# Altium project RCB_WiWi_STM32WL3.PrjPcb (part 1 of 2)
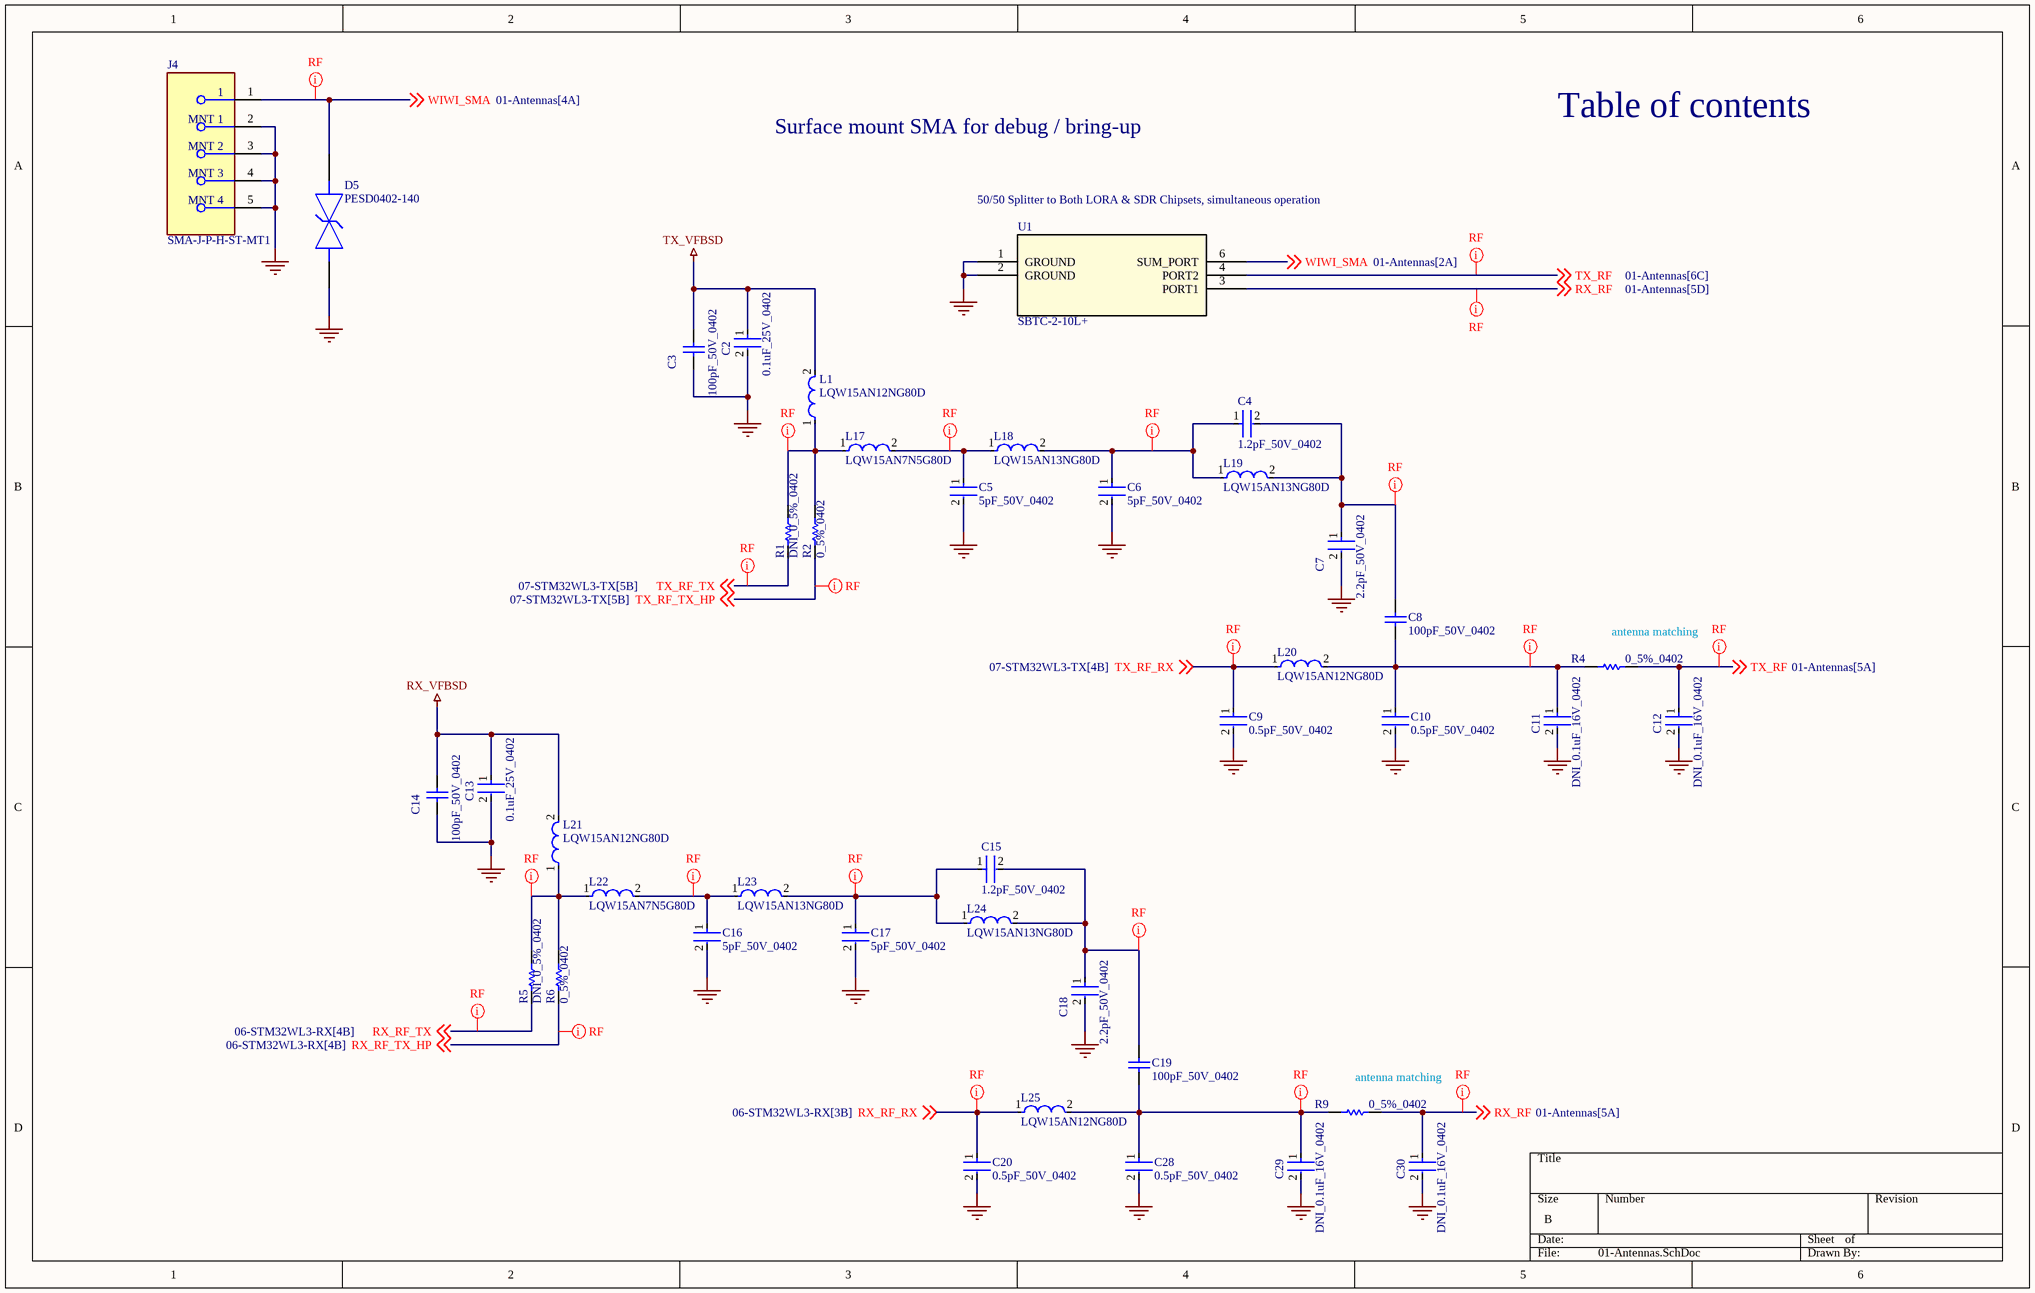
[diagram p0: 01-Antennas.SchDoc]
prjCompanyName: Meta Platforms Technologies, LLC.; prjContactAddress1: 9845 Willows Road NE; prjContactAddress2: Redmond, WA 98052; prjContactEmail: Contact Email; prjContactPhone: (...)-...-....; prjElectricalEngineer: Electical Engineer; prjElectricalEngineerEmail: Electical Engineer Email; prjLayoutEngineer: Layout Engineer; prjLayoutEngineerEmail: Layout Engineer Email; prjMechanicalEngineer: Mechanical Engineer; prjMechanicalEngineerEmail: Mechanical Engineer Email; prjPCB_IPN: 844-XXXXX-XX; prjPCB_Name: PCB Name; prjPCB_Revision: X1; prjProjectName: Project Name; prjSchematic_IPN: 846-XXXXX-XX; prjSchematic_Revision: X1; XprjPCBA_IPN: Set v_prjPCBA_IPN in variant parameters; XprjPCBA_Revision: Set v_prjPCBA_Revision in variant parameters
8 sheets, 342 parts. Net scope: global (net labels, ports and power ports of the same name join across sheets).
Board file: RCB_WiWi_STM32WL3_V1.PcbDoc
Sheets:
  01-Antennas.SchDoc
  02-8A34004_DPLL-1.SchDoc
  03-8A34004_DPLL-2.SchDoc
  04-TCXO_Crystal.SchDoc
  05-USB-Prog.SchDoc
  06-STM32WL3-RX.SchDoc
  07-STM32WL3-TX.SchDoc
  08-Power.SchDoc

## Sheet 01-Antennas.SchDoc
size B; SheetNumber: 1; SheetTotal: 8; SPICEModelCacheELOCFEDZ: <root> / <DocumentId>ELOCFEDZ</DocumentId> / </root>

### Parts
C2  0.1uF_25V_0402  [FP-0402-L_1_0_1-W_0_5_0_1-IPC_C]
C3  100pF_50V_0402  [CAPC1005X55X25ML05T10]
C4  1.2pF_50V_0402  [FP-GJM155-0_05-IPC_A]
C5  5pF_50V_0402  [FP-GJM155-0_05-IPC_B]
C6  5pF_50V_0402  [FP-GJM155-0_05-IPC_B]
C7  2.2pF_50V_0402  [FP-GJM155-0_05-IPC_C]
C8  100pF_50V_0402  [CAPC1005X55X25ML05T10]
C9  0.5pF_50V_0402  [FP-GJM155-0_05-MFG]
C10  0.5pF_50V_0402  [FP-GJM155-0_05-MFG]
C11  DNI_0.1uF_16V_0402  [FP-C0402-BB-MFG]  (no BOM)
C12  DNI_0.1uF_16V_0402  [FP-C0402-BB-MFG]  (no BOM)
C13  0.1uF_25V_0402  [FP-0402-L_1_0_1-W_0_5_0_1-IPC_C]
C14  100pF_50V_0402  [CAPC1005X55X25ML05T10]
C15  1.2pF_50V_0402  [FP-GJM155-0_05-IPC_A]
C16  5pF_50V_0402  [FP-GJM155-0_05-IPC_B]
C17  5pF_50V_0402  [FP-GJM155-0_05-IPC_B]
C18  2.2pF_50V_0402  [FP-GJM155-0_05-IPC_C]
C19  100pF_50V_0402  [CAPC1005X55X25ML05T10]
C20  0.5pF_50V_0402  [FP-GJM155-0_05-MFG]
C28  0.5pF_50V_0402  [FP-GJM155-0_05-MFG]
C29  DNI_0.1uF_16V_0402  [FP-C0402-BB-MFG]  (no BOM)
C30  DNI_0.1uF_16V_0402  [FP-C0402-BB-MFG]  (no BOM)
D5  PESD0402-140  [FP-PESD0402-MFG]
J4  SMA-J-P-H-ST-MT1  [FP-SMA-J-P-H-ST-MT1-MFG]
L1  LQW15AN12NG80D  [FP-LQW15AN_80-MFG]
L17  LQW15AN7N5G80D  [FP-LQW15AN_80-MFG]
L18  LQW15AN13NG80D  [FP-LQW15AN_80-MFG]
L19  LQW15AN13NG80D  [FP-LQW15AN_80-MFG]
L20  LQW15AN12NG80D  [FP-LQW15AN_80-MFG]
L21  LQW15AN12NG80D  [FP-LQW15AN_80-MFG]
L22  LQW15AN7N5G80D  [FP-LQW15AN_80-MFG]
L23  LQW15AN13NG80D  [FP-LQW15AN_80-MFG]
L24  LQW15AN13NG80D  [FP-LQW15AN_80-MFG]
L25  LQW15AN12NG80D  [FP-LQW15AN_80-MFG]
R1  DNI_0_5%_0402  [RESC1005X40X25NL05T10]  (no BOM)
R2  0_5%_0402  [RESC1005X40X25NL05T10]
R4  0_5%_0402  [RESC1005X40X25NL05T10]
R5  DNI_0_5%_0402  [RESC1005X40X25NL05T10]  (no BOM)
R6  0_5%_0402  [RESC1005X40X25NL05T10]
R9  0_5%_0402  [RESC1005X40X25NL05T10]
U1  SBTC-2-10L+  [AT1029_MNC]

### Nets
GND: C2.2 C3.1 C5.2 C6.2 C7.2 C9.2 C10.2 C11.2 C12.2 C13.2 C14.1 C16.2 C17.2 C18.2 C20.2 C28.2 C29.2 C30.2 D5.1 J4.2(MNT_1) J4.3(MNT_2) J4.4(MNT_3) J4.5(MNT_4) U1.1(GROUND) U1.2(GROUND)
RX_VFBSD: C13.1 C14.2 L21.2
TX_VFBSD: C2.1 C3.2 L1.2
RX_RF: C30.1 R9.2 U1.3(PORT1) ; off-sheet RX_RF
RX_RF_RX: C20.1 L25.1 ; off-sheet RX_RF_RX
RX_RF_TX: R5.1 ; off-sheet RX_RF_TX
RX_RF_TX_HP: R6.1 ; off-sheet RX_RF_TX_HP
TX_RF: C12.1 R4.2 U1.4(PORT2) ; off-sheet TX_RF
TX_RF_RX: C9.1 L20.1 ; off-sheet TX_RF_RX
TX_RF_TX: R1.1 ; off-sheet TX_RF_TX
TX_RF_TX_HP: R2.1 ; off-sheet TX_RF_TX_HP
WIWI_SMA: D5.2 J4.1 U1.6(SUM_PORT) ; off-sheet WIWI_SMA
NetC4_1: C4.1 C6.1 L18.2 L19.1
NetC4_2: C4.2 C7.1 C8.2 L19.2
NetC5_1: C5.1 L17.2 L18.1
NetC8_1: C8.1 C10.1 C11.1 L20.2 R4.1
NetC15_1: C15.1 C17.1 L23.2 L24.1
NetC15_2: C15.2 C18.1 C19.2 L24.2
NetC16_1: C16.1 L22.2 L23.1
NetC19_1: C19.1 C28.1 C29.1 L25.2 R9.1
NetL1_1: L1.1 L17.1 R1.2 R2.2
NetL21_1: L21.1 L22.1 R5.2 R6.2

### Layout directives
net class RF: NetC4_1, NetC4_2, NetC5_1, NetC8_1, NetC15_1, NetC15_2, NetC16_1, NetC19_1, NetL1_1, NetL21_1, RX_RF, RX_RF_RX, RX_RF_TX, RX_RF_TX_HP, TX_RF, TX_RF_RX, TX_RF_TX, TX_RF_TX_HP, WIWI_SMA

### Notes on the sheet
- Surface mount SMA for debug / bring-up
- Table of contents
- 50/50 Splitter to Both LORA & SDR Chipsets, simultaneous operation
- (near R4) antenna matching
- (near R9) antenna matching

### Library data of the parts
C2 C13 = CMP-2008-02519-2: General Purpose Ceramic Capacitor, 0402, 100nF, 10%, X7R, 15%, 25V
C3 C8 C14 C19 = CMP-2008-03915-1: Manufacturer: Murata; Part Number: GRM1555C1H101JA01D
C4 C15 = CMP-2008-03815-2: Multi-Layer Ceramic Capacitor 1.2pF C0G  ±0.05pF 0402 Paper T/R; Voltage Rating: 50V
C5 C6 C16 C17 = CMP-06035-005630-1: Multi-Layer Ceramic Capacitor 5pF C0G  ±0.05pF 0402 Paper T/R; Voltage Rating (DC): 50V
C7 C18 = CMP-2008-03837-2: Multi-Layer Ceramic Capacitor 2.2pF C0G  ±0.05pF 0402 Paper T/R; Voltage Rating: 50V
C9 C10 C20 C28 = CMP-2008-03904-2: Multi-Layer Ceramic Capacitor 0.5pF C0G  ±0.1pF 0402 Paper T/R; Voltage Rating (DC): 50V; Temperature Coefficient: 30ppm/°C
C11 C12 C29 C30 = CMP-1034-02068-3: CAP CER 0.1UF 16V 5% X7R 0402; Manufacturer: Kemet; Manufacturer Part Number: C0402C104J4RACTU; Value: 0.10 μF; Temperature Coefficient: 15%; Tolerance: 0.05; Material: Ceramic
D5 = CMP-08607-000011-1: TVS DIODE 14V 40V 0402; Manufacturer: Littelfuse Inc.; Automotive Grade: Grade 1; Capacitance: 0.25pF; Value: 0.25pF; Direction: Bidirectional; Number Of Channels: 1
J4 = CMP-02754-000007-1: CONN SMA JACK STR 50 OHM SMD; Dielectric Material: PTFE; Voltage Rating: 335V; Body Material: Brass; Center Contact Plating: Gold; Impedance: 50R; Number of Ports: 1; Max Frequency: 20GHz
L1 L20 L21 L25 = CMP-06042-001817-1: Wire Wound RF Inductor 12nH ±2% 1240mA 0.093Ω 0402 (1005); Test Frequency: 100MHz; DC Resistance (DCR): 93mR; Self Resonant Frequency: 5.2GHz; Shielding: Unshielded; Max DC Current: 1.24A; Q Factor: 30; Core Material: Ferrite
L17 L22 = CMP-06042-000856-1: Wire Wound RF Inductor 7.5nH ±2% 1700mA 0.05Ω 0402 (1005); Max DC Current: 1.7A; Shielding: Unshielded; Core Material: Ferrite; Self Resonant Frequency: 7GHz; DC Resistance (DCR): 50mR; Test Frequency: 100MHz; Q Factor: 35
L18 L19 L23 L24 = CMP-06042-008137-1: Wire Wound RF Inductor 13nH ±2% 1240mA 0.093Ω 0402 (1005); Core Material: Ferrite; Q Factor: 30; DC Resistance (DCR): 93mR; Current Rating: 1.24A; Shielding: Unshielded; Test Frequency: 100MHz; Self Resonant Frequency: 5.2GHz
R1 R2 R4-R6 R9 = CMP-2002-06457-1: Manufacturer: Panasonic; Part Number: ERJ-U020R00X
U1 = SBTC-2-10L+: No Description Available; Mfr_Name: Mini Circuits

## Sheet 02-8A34004_DPLL-1.SchDoc
size B; SheetNumber: 2; SheetTotal: 8
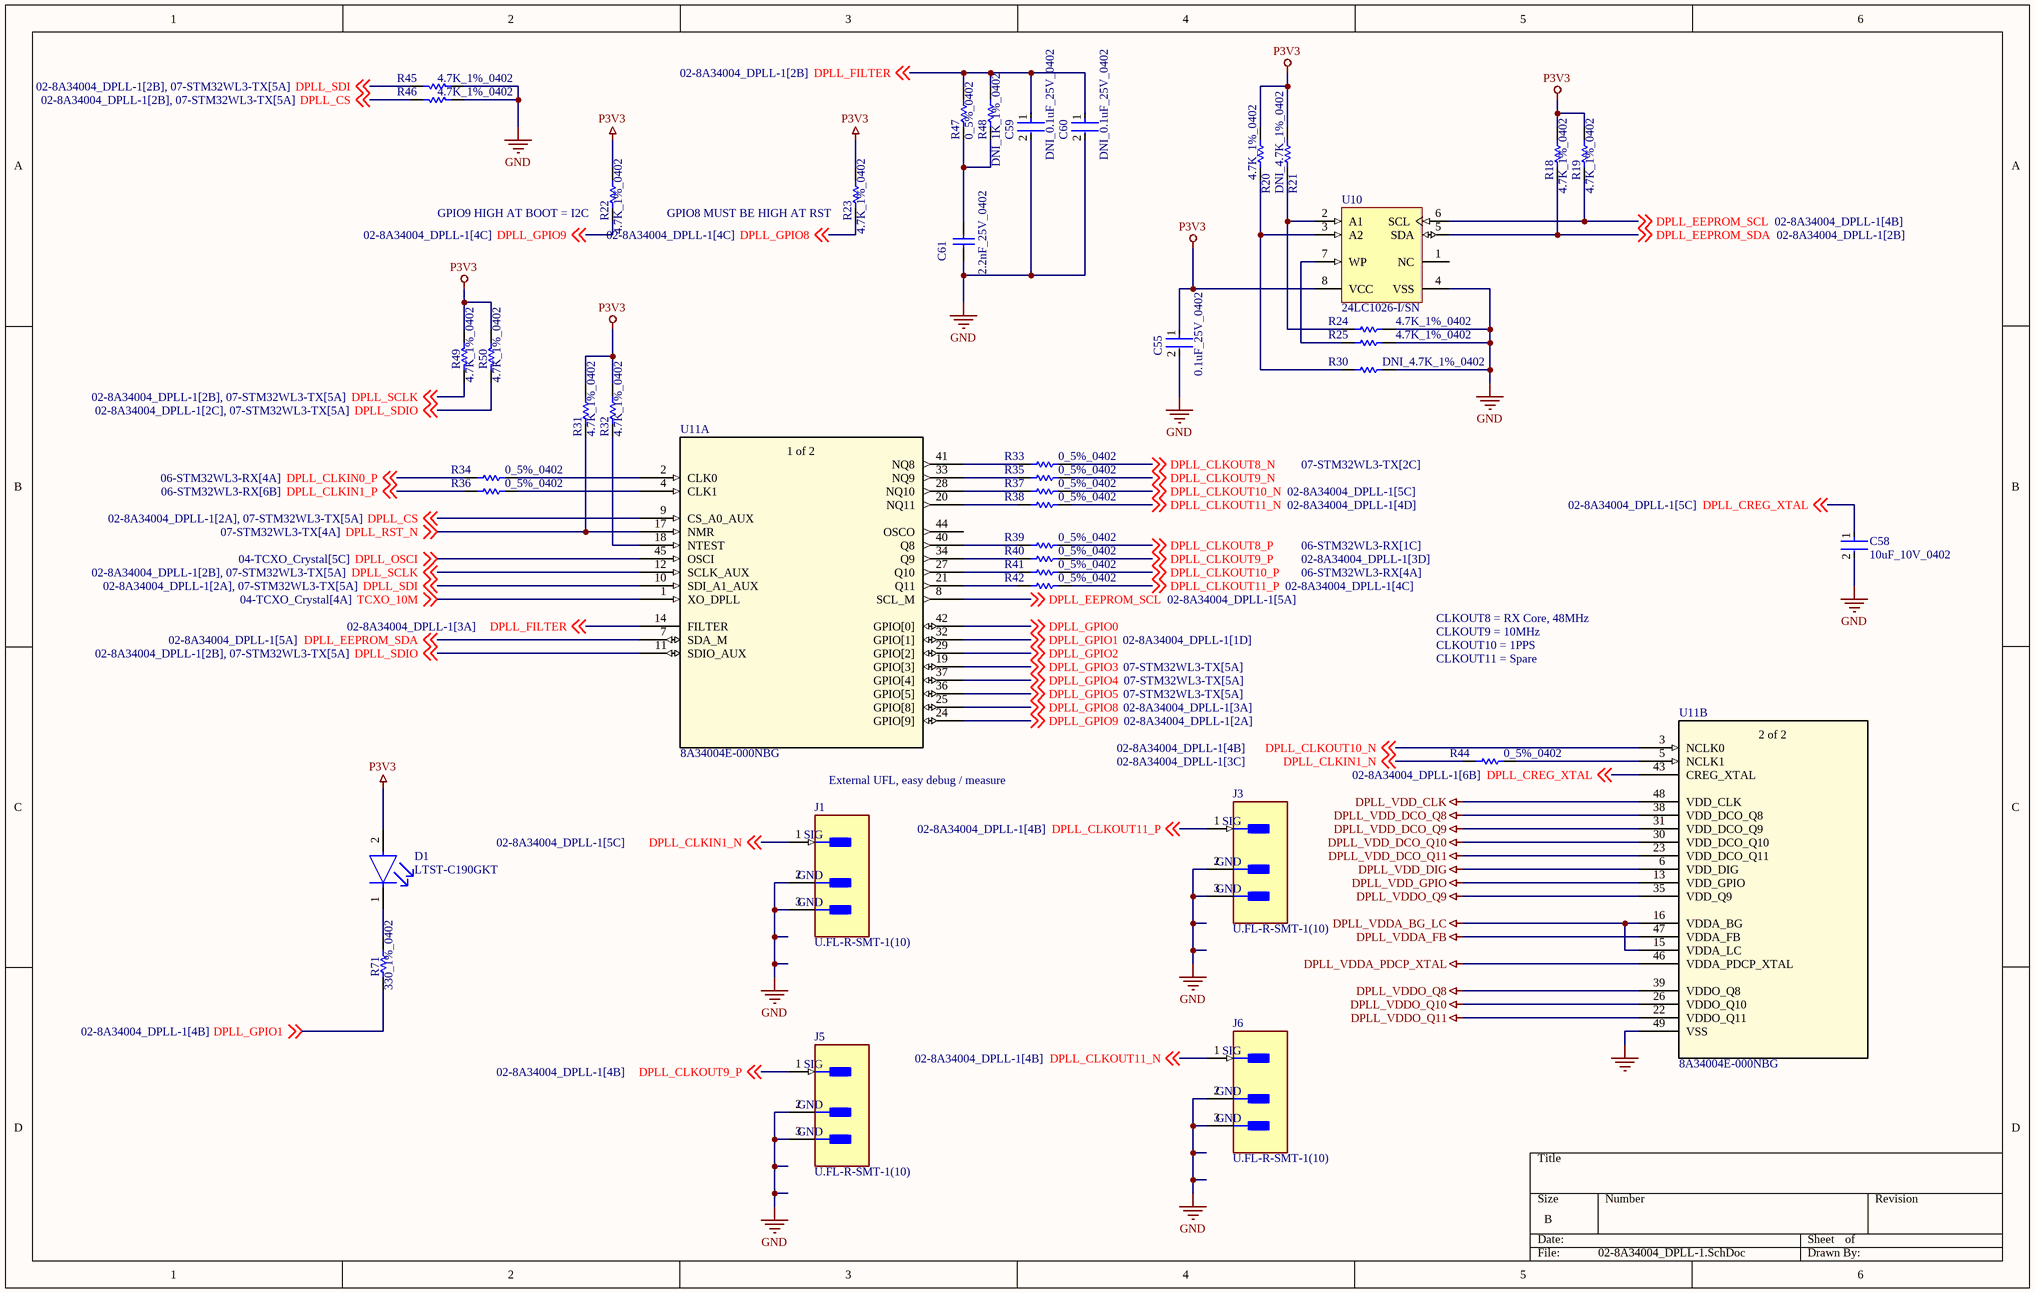
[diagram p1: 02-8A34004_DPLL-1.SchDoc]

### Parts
C55  0.1uF_25V_0402  [FP-0402-L_1_0_1-W_0_5_0_1-IPC_C]
C58  10uF_10V_0402  [FP-CL05A106MP5NUNC-MFG]
C59  DNI_0.1uF_25V_0402  [FP-0402-L_1_0_1-W_0_5_0_1-IPC_C]  (no BOM)
C60  DNI_0.1uF_25V_0402  [FP-0402-L_1_0_1-W_0_5_0_1-IPC_C]  (no BOM)
C61  2.2nF_25V_0402  [CAPC1005X56X25LL10T15]
D1  LTST-C190GKT  [FP-LTST-C190GKT-MFG]
J1  U.FL-R-SMT-1(10)  [FP-U_FL-R-SMT-1_10-MFG]
J3  U.FL-R-SMT-1(10)  [FP-U_FL-R-SMT-1_10-MFG]
J5  U.FL-R-SMT-1(10)  [FP-U_FL-R-SMT-1_10-MFG]
J6  U.FL-R-SMT-1(10)  [FP-U_FL-R-SMT-1_10-MFG]
R18  4.7K_1%_0402  [RESC1005X40X25NL10T10]
R19  4.7K_1%_0402  [RESC1005X40X25NL10T10]
R20  4.7K_1%_0402  [RESC1005X40X25NL10T10]
R21  DNI_4.7K_1%_0402  [RESC1005X40X25NL10T10]  (no BOM)
R22  4.7K_1%_0402  [RESC1005X40X25NL10T10]
R23  4.7K_1%_0402  [RESC1005X40X25NL10T10]
R24  4.7K_1%_0402  [RESC1005X40X25NL10T10]
R25  4.7K_1%_0402  [RESC1005X40X25NL10T10]
R30  DNI_4.7K_1%_0402  [RESC1005X40X25NL10T10]  (no BOM)
R31  4.7K_1%_0402  [RESC1005X40X25NL10T10]
R32  4.7K_1%_0402  [RESC1005X40X25NL10T10]
R33  0_5%_0402  [RESC1005X40X25NL05T10]
R34  0_5%_0402  [RESC1005X40X25NL05T10]
R35  0_5%_0402  [RESC1005X40X25NL05T10]
R36  0_5%_0402  [RESC1005X40X25NL05T10]
R37  0_5%_0402  [RESC1005X40X25NL05T10]
R38  0_5%_0402  [RESC1005X40X25NL05T10]
R39  0_5%_0402  [RESC1005X40X25NL05T10]
R40  0_5%_0402  [RESC1005X40X25NL05T10]
R41  0_5%_0402  [RESC1005X40X25NL05T10]
R42  0_5%_0402  [RESC1005X40X25NL05T10]
R44  0_5%_0402  [RESC1005X40X25NL05T10]
R45  4.7K_1%_0402  [RESC1005X40X25NL10T10]
R46  4.7K_1%_0402  [RESC1005X40X25NL10T10]
R47  0_5%_0402  [RESC1005X40X25LL10T10]
R48  DNI_1K_1%_0402  [RESC1005X40X25NL05T05]  (no BOM)
R49  4.7K_1%_0402  [RESC1005X40X25NL10T10]
R50  4.7K_1%_0402  [RESC1005X40X25NL10T10]
R71  330_1%_0402  [RESC1005X40X25NL10T10]
U10  24LC1026-I/SN  [MCHP-SOIC-SN8_N]
U11  8A34004E-000NBG  [NBG48P1_REN]  (parts A,B of 2)

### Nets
DPLL_VDD_CLK: U11.48(VDD_CLK)
DPLL_VDD_DCO_Q8: U11.38(VDD_DCO_Q8)
DPLL_VDD_DCO_Q9: U11.31(VDD_DCO_Q9)
DPLL_VDD_DCO_Q10: U11.30(VDD_DCO_Q10)
DPLL_VDD_DCO_Q11: U11.23(VDD_DCO_Q11)
DPLL_VDD_DIG: U11.6(VDD_DIG)
DPLL_VDD_GPIO: U11.13(VDD_GPIO)
DPLL_VDDA_BG_LC: U11.15(VDDA_LC) U11.16(VDDA_BG)
DPLL_VDDA_FB: U11.47(VDDA_FB)
DPLL_VDDA_PDCP_XTAL: U11.46(VDDA_PDCP_XTAL)
DPLL_VDDO_Q8: U11.39(VDDO_Q8)
DPLL_VDDO_Q9: U11.35(VDD_Q9)
DPLL_VDDO_Q10: U11.26(VDDO_Q10)
DPLL_VDDO_Q11: U11.22(VDDO_Q11)
GND: C55.2 C58.2 C59.2 C60.2 C61.1 J1.2(GND) J1.3(GND) J3.2(GND) J3.3(GND) J5.2(GND) J5.3(GND) J6.2(GND) J6.3(GND) R24.1 R25.1 R30.2 R45.2 R46.2 U10.4(VSS) U11.49(VSS)
P3V3: C55.1 D1.2(A) R18.1 R19.1 R20.2 R21.2 R22.1 R23.1 R31.2 R32.2 R49.2 R50.2 U10.8(VCC)
DPLL_CLKIN0_P: R34.1 ; off-sheet DPLL_CLKIN0_P
DPLL_CLKIN1_N: J1.1(SIG) R44.1 ; off-sheet DPLL_CLKIN1_N
DPLL_CLKIN1_P: R36.1 ; off-sheet DPLL_CLKIN1_P
DPLL_CLKOUT8_N: R33.2 ; off-sheet DPLL_CLKOUT8_N
DPLL_CLKOUT8_P: R39.2 ; off-sheet DPLL_CLKOUT8_P
DPLL_CLKOUT9_N: R35.2 ; off-sheet DPLL_CLKOUT9_N
DPLL_CLKOUT9_P: J5.1(SIG) R40.2 ; off-sheet DPLL_CLKOUT9_P
DPLL_CLKOUT10_N: R37.2 U11.3(NCLK0) ; off-sheet DPLL_CLKOUT10_N
DPLL_CLKOUT10_P: R41.2 ; off-sheet DPLL_CLKOUT10_P
DPLL_CLKOUT11_N: J6.1(SIG) R38.2 ; off-sheet DPLL_CLKOUT11_N
DPLL_CLKOUT11_P: J3.1(SIG) R42.2 ; off-sheet DPLL_CLKOUT11_P
DPLL_CREG_XTAL: C58.1 U11.43(CREG_XTAL) ; off-sheet DPLL_CREG_XTAL
DPLL_CS: R46.1 U11.9(CS_A0_AUX) ; off-sheet DPLL_CS
DPLL_EEPROM_SCL: R19.2 U10.6(SCL) U11.8(SCL_M) ; off-sheet DPLL_EEPROM_SCL
DPLL_EEPROM_SDA: R18.2 U10.5(SDA) U11.7(SDA_M) ; off-sheet DPLL_EEPROM_SDA
DPLL_FILTER: C59.1 C60.1 R47.2 R48.2 U11.14(FILTER) ; off-sheet DPLL_FILTER
DPLL_GPIO0: U11.42(GPIO[0]) ; off-sheet DPLL_GPIO0
DPLL_GPIO1: R71.1 U11.32(GPIO[1]) ; off-sheet DPLL_GPIO1
DPLL_GPIO2: U11.29(GPIO[2]) ; off-sheet DPLL_GPIO2
DPLL_GPIO3: U11.19(GPIO[3]) ; off-sheet DPLL_GPIO3
DPLL_GPIO4: U11.37(GPIO[4]) ; off-sheet DPLL_GPIO4
DPLL_GPIO5: U11.36(GPIO[5]) ; off-sheet DPLL_GPIO5
DPLL_GPIO8: R23.2 U11.25(GPIO[8]) ; off-sheet DPLL_GPIO8
DPLL_GPIO9: R22.2 U11.24(GPIO[9]) ; off-sheet DPLL_GPIO9
DPLL_OSCI: U11.45(OSCI) ; off-sheet DPLL_OSCI
DPLL_RST_N: R31.1 U11.17(NMR) ; off-sheet DPLL_RST_N
DPLL_SCLK: R49.1 U11.12(SCLK_AUX) ; off-sheet DPLL_SCLK
DPLL_SDI: R45.1 U11.10(SDI_A1_AUX) ; off-sheet DPLL_SDI
DPLL_SDIO: R50.1 U11.11(SDIO_AUX) ; off-sheet DPLL_SDIO
TCXO_10M: U11.1(XO_DPLL) ; off-sheet TCXO_10M
NetC61_2: C61.2 R47.1 R48.1
NetD1_1: D1.1(C) R71.2
NetR20_1: R20.1 R30.1 U10.3(A2)
NetR21_1: R21.1 R24.2 U10.2(A1)
NetR25_2: R25.2 U10.7(WP)
NetR32_1: R32.1 U11.18(NTEST)
NetR33_1: R33.1 U11.41(NQ8)
NetR34_2: R34.2 U11.2(CLK0)
NetR35_1: R35.1 U11.33(NQ9)
NetR36_2: R36.2 U11.4(CLK1)
NetR37_1: R37.1 U11.28(NQ10)
NetR38_1: R38.1 U11.20(NQ11)
NetR39_1: R39.1 U11.40(Q8)
NetR40_1: R40.1 U11.34(Q9)
NetR41_1: R41.1 U11.27(Q10)
NetR42_1: R42.1 U11.21(Q11)
NetR44_2: R44.2 U11.5(NCLK1)

Not connected (* = marked no-connect by the designer): U10 1(NC); U11 44(OSCO)

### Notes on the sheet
- (near R22) GPIO9 HIGH AT BOOT = I2C
- GPIO8 MUST BE HIGH AT RST
- CLKOUT8 = RX Core, 48MHz
- CLKOUT9 = 10MHz
- CLKOUT10 = 1PPS
- CLKOUT11 = Spare
- External UFL, easy debug / measure

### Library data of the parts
C55 C59 C60 = CMP-2008-02519-2: as C2 on sheet 01-Antennas
C58 = CMP-13271-000002-1: CAP CER 10UF 10V X5R 0402; Manufacturer Part Number: CL05A106MP5NUNC; Manufacturer: Samsung; Temperature Coefficient: 15%; Tolerance: 20%; Material: Ceramic
C61 = CMP-2008-02907-1: Manufacturer: AVX Interconnect / Elco; Part Number: 04025C222JAT2A
D1 = CMP-22017-000005-2: LED GREEN CLEAR CHIP SMD; Dominant Wavelength: 569nm; Reverse Voltage: 5V; Lens Color: Colorless; Viewing Angle: 130°; Voltage: 2V; Forward Current: 30mA; Power Dissipation: 100mW; Luminous Intensity: 6mcd; Number of LEDs: 1; Forward Voltage: 2.1V; Wavelength: 565nm; Test Current: 10mA
J1 J3 J5 J6 = CMP-2000-05152-3: CONN U.FL RCPT STR 50 OHM SMD; Max Frequency: 6GHz; Connector Type: Coaxial; Body Plating: Silver; Body Material: Bronze; Impedance: 50R; Dielectric Material: Polymer; Insulation Resistance: 500MR; Gender: Male
R18-R25 R30-R32 R45 R46 R49 R50 = CMP-2002-05217-1: Manufacturer: Bourns; Part Number: CR0402-FX-4701GLF
R33-R42 R44 = CMP-2002-06457-1: as R1 on sheet 01-Antennas
R47 = CMP-2002-04569-1: Manufacturer: KOA Speer; Part Number: RK73Z1ETTP
R48 = CMP-2002-08277-1: Manufacturer: Vishay Dale; Part Number: CRCW04021K00FKTD
R71 = CMP-2002-05853-1: Manufacturer: Panasonic; Part Number: ERA-2AED331X
U10 = CMP-0159-01024-1: 1024K bits I2C™ Serial EEPROM, 2.5 to 5.5 V, 400 kHz, -40 to 85 degC, 8-pin SOIC (SN8), Tube; Manufacturer: Microchip
U11 = 8A34004E-000NBG: No Description Available; Mfr_Name: Renesas Electronics

## Sheet 03-8A34004_DPLL-2.SchDoc
size B; SheetNumber: 4; SheetTotal: 8
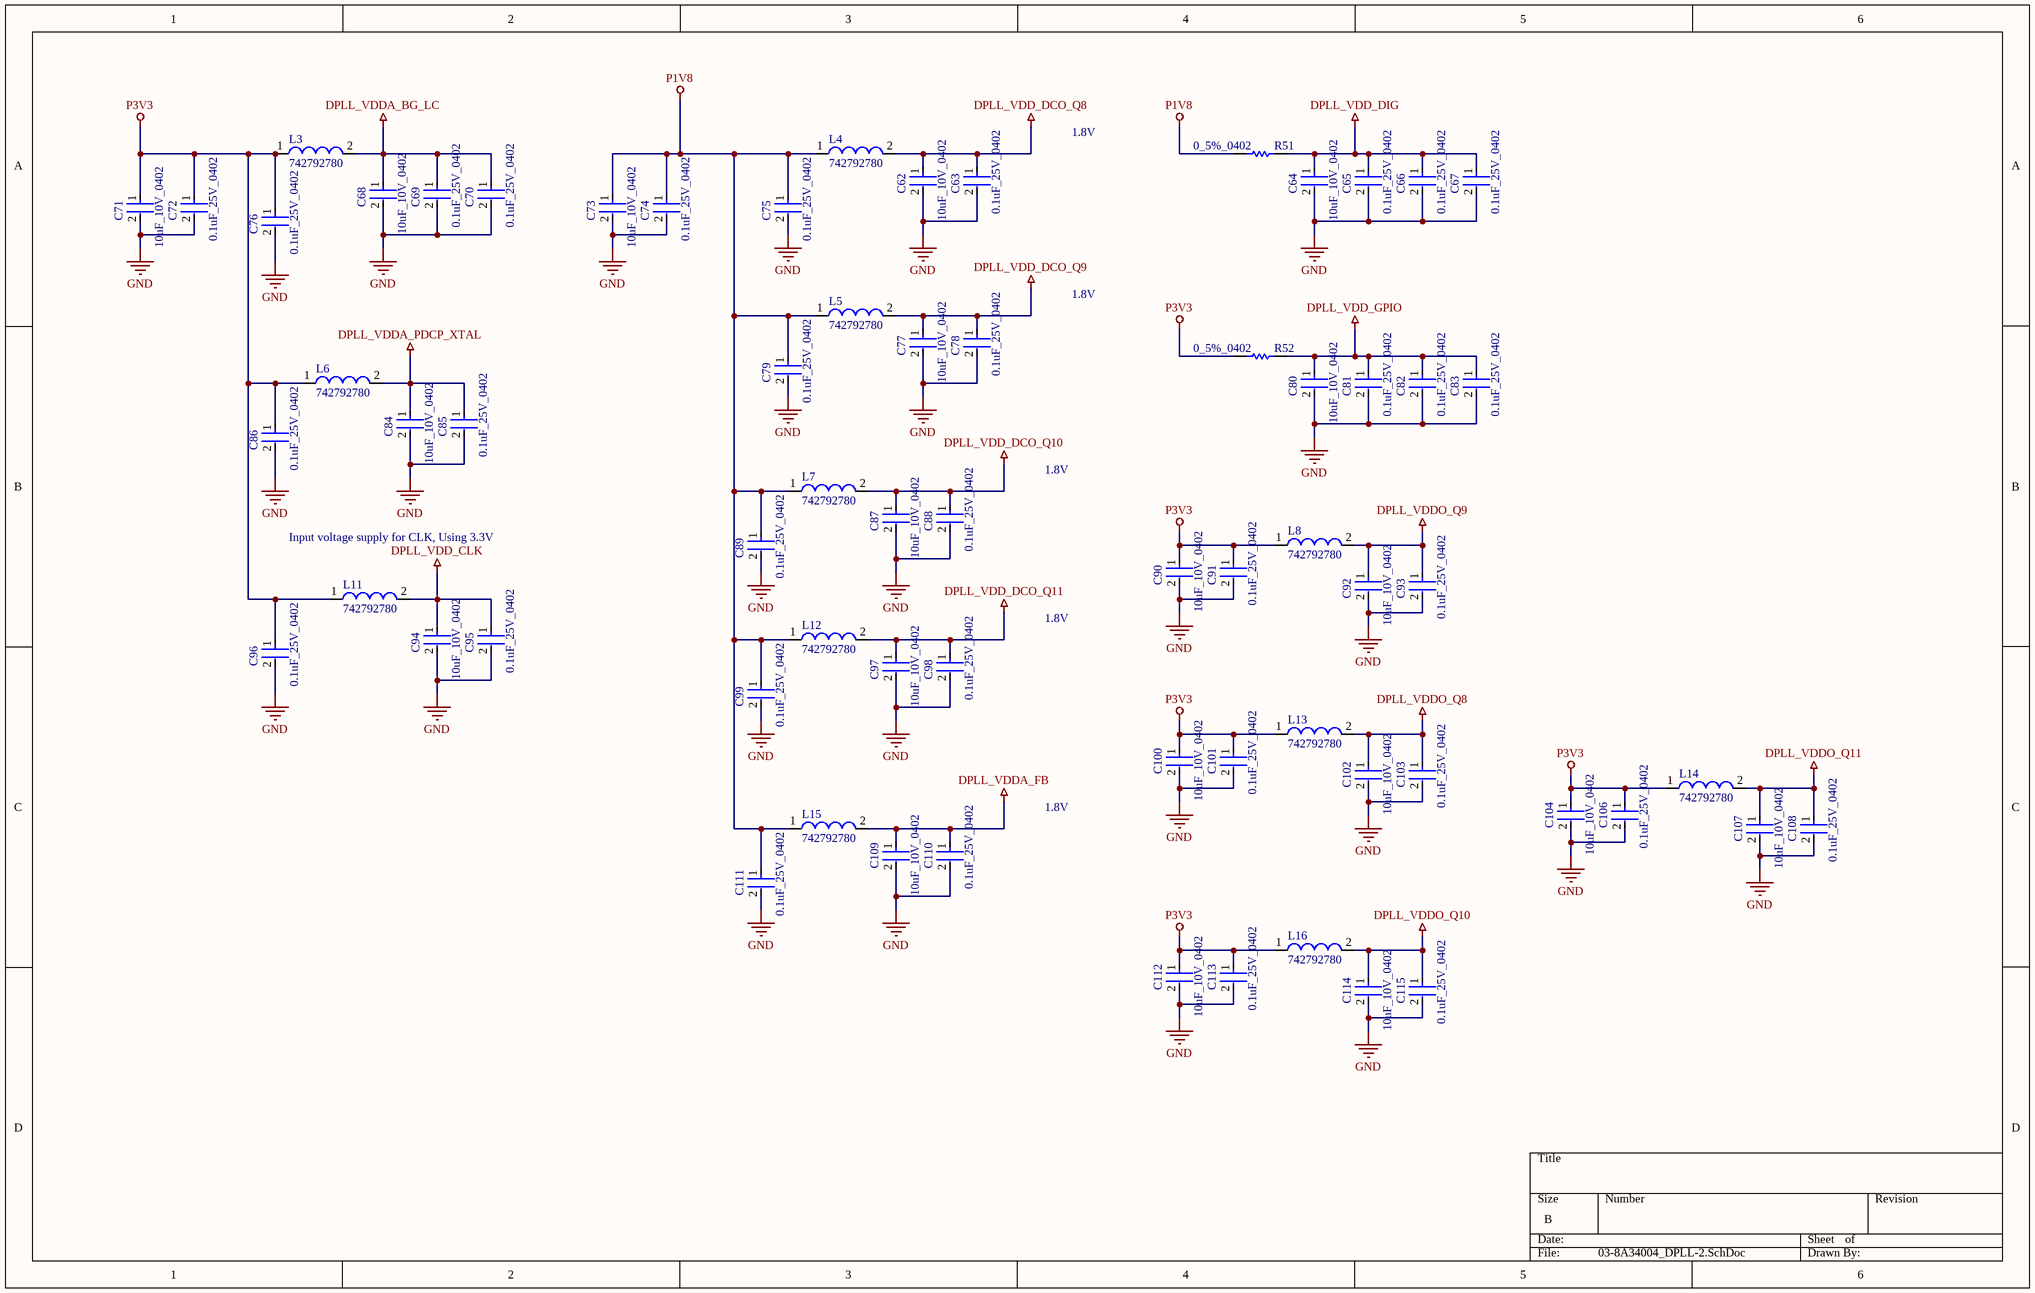
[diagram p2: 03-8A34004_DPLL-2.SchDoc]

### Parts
C62  10uF_10V_0402  [FP-CL05A106MP5NUNC-MFG]
C63  0.1uF_25V_0402  [FP-0402-L_1_0_1-W_0_5_0_1-IPC_C]
C64  10uF_10V_0402  [FP-CL05A106MP5NUNC-MFG]
C65  0.1uF_25V_0402  [FP-0402-L_1_0_1-W_0_5_0_1-IPC_C]
C66  0.1uF_25V_0402  [FP-0402-L_1_0_1-W_0_5_0_1-IPC_C]
C67  0.1uF_25V_0402  [FP-0402-L_1_0_1-W_0_5_0_1-IPC_C]
C68  10uF_10V_0402  [FP-CL05A106MP5NUNC-MFG]
C69  0.1uF_25V_0402  [FP-0402-L_1_0_1-W_0_5_0_1-IPC_C]
C70  0.1uF_25V_0402  [FP-0402-L_1_0_1-W_0_5_0_1-IPC_C]
C71  10uF_10V_0402  [FP-CL05A106MP5NUNC-MFG]
C72  0.1uF_25V_0402  [FP-0402-L_1_0_1-W_0_5_0_1-IPC_C]
C73  10uF_10V_0402  [FP-CL05A106MP5NUNC-MFG]
C74  0.1uF_25V_0402  [FP-0402-L_1_0_1-W_0_5_0_1-IPC_C]
C75  0.1uF_25V_0402  [FP-0402-L_1_0_1-W_0_5_0_1-IPC_C]
C76  0.1uF_25V_0402  [FP-0402-L_1_0_1-W_0_5_0_1-IPC_C]
C77  10uF_10V_0402  [FP-CL05A106MP5NUNC-MFG]
C78  0.1uF_25V_0402  [FP-0402-L_1_0_1-W_0_5_0_1-IPC_C]
C79  0.1uF_25V_0402  [FP-0402-L_1_0_1-W_0_5_0_1-IPC_C]
C80  10uF_10V_0402  [FP-CL05A106MP5NUNC-MFG]
C81  0.1uF_25V_0402  [FP-0402-L_1_0_1-W_0_5_0_1-IPC_C]
C82  0.1uF_25V_0402  [FP-0402-L_1_0_1-W_0_5_0_1-IPC_C]
C83  0.1uF_25V_0402  [FP-0402-L_1_0_1-W_0_5_0_1-IPC_C]
C84  10uF_10V_0402  [FP-CL05A106MP5NUNC-MFG]
C85  0.1uF_25V_0402  [FP-0402-L_1_0_1-W_0_5_0_1-IPC_C]
C86  0.1uF_25V_0402  [FP-0402-L_1_0_1-W_0_5_0_1-IPC_C]
C87  10uF_10V_0402  [FP-CL05A106MP5NUNC-MFG]
C88  0.1uF_25V_0402  [FP-0402-L_1_0_1-W_0_5_0_1-IPC_C]
C89  0.1uF_25V_0402  [FP-0402-L_1_0_1-W_0_5_0_1-IPC_C]
C90  10uF_10V_0402  [FP-CL05A106MP5NUNC-MFG]
C91  0.1uF_25V_0402  [FP-0402-L_1_0_1-W_0_5_0_1-IPC_C]
C92  10uF_10V_0402  [FP-CL05A106MP5NUNC-MFG]
C93  0.1uF_25V_0402  [FP-0402-L_1_0_1-W_0_5_0_1-IPC_C]
C94  10uF_10V_0402  [FP-CL05A106MP5NUNC-MFG]
C95  0.1uF_25V_0402  [FP-0402-L_1_0_1-W_0_5_0_1-IPC_C]
C96  0.1uF_25V_0402  [FP-0402-L_1_0_1-W_0_5_0_1-IPC_C]
C97  10uF_10V_0402  [FP-CL05A106MP5NUNC-MFG]
C98  0.1uF_25V_0402  [FP-0402-L_1_0_1-W_0_5_0_1-IPC_C]
C99  0.1uF_25V_0402  [FP-0402-L_1_0_1-W_0_5_0_1-IPC_C]
C100  10uF_10V_0402  [FP-CL05A106MP5NUNC-MFG]
C101  0.1uF_25V_0402  [FP-0402-L_1_0_1-W_0_5_0_1-IPC_C]
C102  10uF_10V_0402  [FP-CL05A106MP5NUNC-MFG]
C103  0.1uF_25V_0402  [FP-0402-L_1_0_1-W_0_5_0_1-IPC_C]
C104  10uF_10V_0402  [FP-CL05A106MP5NUNC-MFG]
C106  0.1uF_25V_0402  [FP-0402-L_1_0_1-W_0_5_0_1-IPC_C]
C107  10uF_10V_0402  [FP-CL05A106MP5NUNC-MFG]
C108  0.1uF_25V_0402  [FP-0402-L_1_0_1-W_0_5_0_1-IPC_C]
C109  10uF_10V_0402  [FP-CL05A106MP5NUNC-MFG]
C110  0.1uF_25V_0402  [FP-0402-L_1_0_1-W_0_5_0_1-IPC_C]
C111  0.1uF_25V_0402  [FP-0402-L_1_0_1-W_0_5_0_1-IPC_C]
C112  10uF_10V_0402  [FP-CL05A106MP5NUNC-MFG]
C113  0.1uF_25V_0402  [FP-0402-L_1_0_1-W_0_5_0_1-IPC_C]
C114  10uF_10V_0402  [FP-CL05A106MP5NUNC-MFG]
C115  0.1uF_25V_0402  [FP-0402-L_1_0_1-W_0_5_0_1-IPC_C]
L3  742792780  [SMD-0402]
L4  742792780  [SMD-0402]
L5  742792780  [SMD-0402]
L6  742792780  [SMD-0402]
L7  742792780  [SMD-0402]
L8  742792780  [SMD-0402]
L11  742792780  [SMD-0402]
L12  742792780  [SMD-0402]
L13  742792780  [SMD-0402]
L14  742792780  [SMD-0402]
L15  742792780  [SMD-0402]
L16  742792780  [SMD-0402]
R51  0_5%_0402  [RESC1005X40X25LL10T10]
R52  0_5%_0402  [RESC1005X40X25LL10T10]

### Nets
DPLL_VDD_CLK: C94.1 C95.1 L11.2
DPLL_VDD_DCO_Q8: C62.1 C63.1 L4.2
DPLL_VDD_DCO_Q9: C77.1 C78.1 L5.2
DPLL_VDD_DCO_Q10: C87.1 C88.1 L7.2
DPLL_VDD_DCO_Q11: C97.1 C98.1 L12.2
DPLL_VDD_DIG: C64.1 C65.1 C66.1 C67.1 R51.2
DPLL_VDD_GPIO: C80.1 C81.1 C82.1 C83.1 R52.2
DPLL_VDDA_BG_LC: C68.1 C69.1 C70.1 L3.2
DPLL_VDDA_FB: C109.1 C110.1 L15.2
DPLL_VDDA_PDCP_XTAL: C84.1 C85.1 L6.2
DPLL_VDDO_Q8: C102.1 C103.1 L13.2
DPLL_VDDO_Q9: C92.1 C93.1 L8.2
DPLL_VDDO_Q10: C114.1 C115.1 L16.2
DPLL_VDDO_Q11: C107.1 C108.1 L14.2
GND: C62.2 C63.2 C64.2 C65.2 C66.2 C67.2 C68.2 C69.2 C70.2 C71.2 C72.2 C73.2 C74.2 C75.2 C76.2 C77.2 C78.2 C79.2 C80.2 C81.2 C82.2 C83.2 C84.2 C85.2 C86.2 C87.2 C88.2 C89.2 C90.2 C91.2 C92.2 C93.2 C94.2 C95.2 C96.2 C97.2 C98.2 C99.2 C100.2 C101.2 C102.2 C103.2 C104.2 C106.2 C107.2 C108.2 C109.2 C110.2 C111.2 C112.2 C113.2 C114.2 C115.2
P1V8: C73.1 C74.1 C75.1 C79.1 C89.1 C99.1 C111.1 L4.1 L5.1 L7.1 L12.1 L15.1 R51.1
P3V3: C71.1 C72.1 C76.1 C86.1 C90.1 C91.1 C96.1 C100.1 C101.1 C104.1 C106.1 C112.1 C113.1 L3.1 L6.1 L8.1 L11.1 L13.1 L14.1 L16.1 R52.1

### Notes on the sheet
- 1.8V
- Input voltage supply for CLK, Using 3.3V

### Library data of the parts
C62 C64 C68 C71 C73 C77 C80 C84 C87 C90 C92 C94 C97 C100 C102 C104 C107 C109 C112 C114 = CMP-13271-000002-1: as C58 on sheet 02-8A34004_DPLL-1
C63 C65-C67 C69 C70 C72 C74-C76 C78 C79 C81-C83 C85 C86 C88 C89 C91 C93 C95 C96 C98 C99 C101 C103 C106 C108 C110 C111 C113 C115 = CMP-2008-02519-2: as C2 on sheet 01-Antennas
L3-L8 L11-L16 = CMP-0220-00137-1: SMD EMI Suppression Ferrite Bead WE-CBF, Z = 220 Ohm; Impedance: 220 Ohm
R51 R52 = CMP-2002-04569-1: as R47 on sheet 02-8A34004_DPLL-1

## Sheet 04-TCXO_Crystal.SchDoc
size B; SheetNumber: 4; SheetTotal: 7
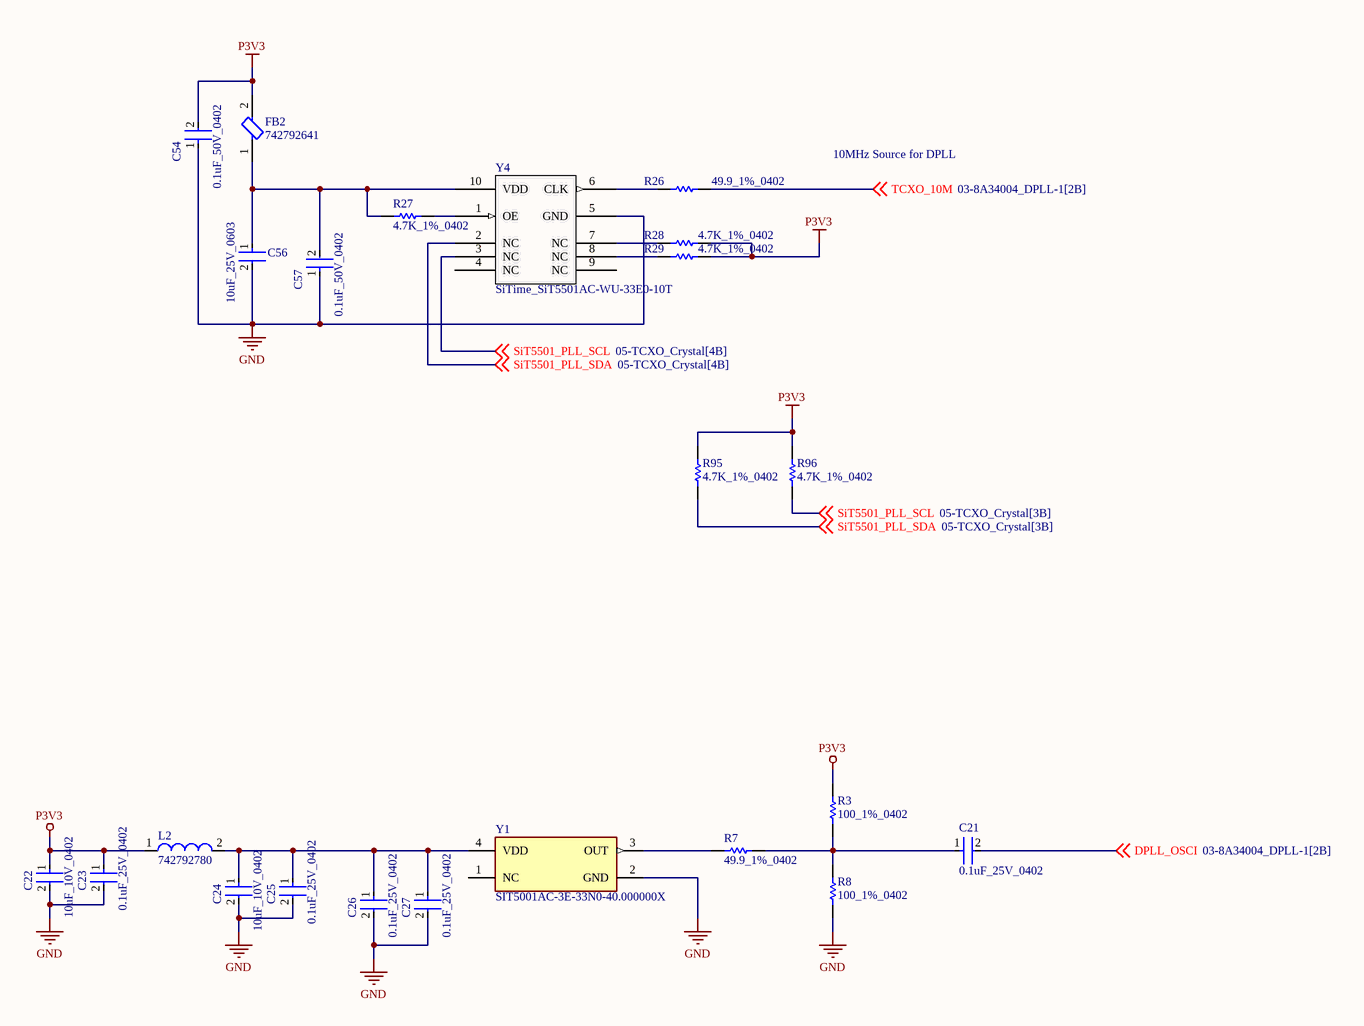
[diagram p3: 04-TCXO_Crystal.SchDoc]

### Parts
C21  0.1uF_25V_0402  [FP-0402-L_1_0_1-W_0_5_0_1-IPC_C]
C22  10uF_10V_0402  [FP-CL05A106MP5NUNC-MFG]
C23  0.1uF_25V_0402  [FP-0402-L_1_0_1-W_0_5_0_1-IPC_C]
C24  10uF_10V_0402  [FP-CL05A106MP5NUNC-MFG]
C25  0.1uF_25V_0402  [FP-0402-L_1_0_1-W_0_5_0_1-IPC_C]
C26  0.1uF_25V_0402  [FP-0402-L_1_0_1-W_0_5_0_1-IPC_C]
C27  0.1uF_25V_0402  [FP-0402-L_1_0_1-W_0_5_0_1-IPC_C]
C54  0.1uF_50V_0402  [FP-C1005-050-0_05-IPC_C]
C56  10uF_25V_0603  [FP-CL10-IPC_C]
C57  0.1uF_50V_0402  [FP-C1005-050-0_05-IPC_C]
FB2  742792641  [FP-742792641-MFG]
L2  742792780  [SMD-0402]
R3  100_1%_0402  [RESC1005X40X25ML05T10]
R7  49.9_1%_0402  [RESC1005X40X25NL10T10]
R8  100_1%_0402  [RESC1005X40X25ML05T10]
R26  49.9_1%_0402  [RESC1005X40X25NL10T10]
R27  4.7K_1%_0402  [RESC1005X40X25NL10T10]
R28  4.7K_1%_0402  [RESC1005X40X25NL10T10]
R29  4.7K_1%_0402  [RESC1005X40X25NL10T10]
R95  4.7K_1%_0402  [RESC1005X40X25NL10T10]
R96  4.7K_1%_0402  [RESC1005X40X25NL10T10]
Y1  SIT5001AC-3E-33N0-40.000000X  [FP-SiT5001-3-MFG]
Y4  SiTime_SiT5501AC-WU-33E0-10T  [SITIME_SPL-086-CQFN-010-C07050_REV_DRAFT]

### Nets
GND: C22.2 C23.2 C24.2 C25.2 C26.2 C27.2 C54.1 C56.2 C57.1 R8.1 Y1.2(GND) Y4.5(GND)
P3V3: C22.1 C23.1 C54.2 FB2.2 L2.1 R3.2 R28.2 R29.2 R95.2 R96.2
DPLL_OSCI: C21.2 ; off-sheet DPLL_OSCI
SiT5501_PLL_SCL: R96.1 Y4.3(NC) ; off-sheet SiT5501_PLL_SCL
SiT5501_PLL_SDA: R95.1 Y4.2(NC) ; off-sheet SiT5501_PLL_SDA
TCXO_10M: R26.1 ; off-sheet TCXO_10M
NetC21_1: C21.1 R3.1 R7.2 R8.2
NetC24_1: C24.1 C25.1 C26.1 C27.1 L2.2 Y1.4(VDD)
NetC56_1: C56.1 C57.2 FB2.1 R27.1 Y4.10(VDD)
NetR7_1: R7.1 Y1.3(OUT)
NetR26_2: R26.2 Y4.6(CLK)
NetR27_2: R27.2 Y4.1(OE)
NetR28_1: R28.1 Y4.7(NC)
NetR29_1: R29.1 Y4.8(NC)

Not connected (* = marked no-connect by the designer): Y1 1(NC); Y4 4(NC) 9(NC)

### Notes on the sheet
- 10MHz Source for DPLL

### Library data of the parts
C21 C23 C25-C27 = CMP-2008-02519-2: as C2 on sheet 01-Antennas
C22 C24 = CMP-13271-000002-1: as C58 on sheet 02-8A34004_DPLL-1
C54 C57 = CMP-2000-05393-2: Multilayer Ceramic Capacitors 100nF ±10% 50V X7R SMD 0402
C56 = CMP-13271-004224-1: Cap Ceramic 10uF 25V X5R ±20% Pad SMD 0603 +85°C T/R
FB2 = CMP-0220-00171-2: FERRITE BEAD 300 OHM 0603 1LN; Inductance: 18nH; Max DC Current: 2A; Number of Lines: 1; Test Frequency: 100MHz; Impedance: 300R; DC Resistance (DCR): 150mR; Tolerance: 25%
L2 = CMP-0220-00137-1: as L3 on sheet 03-8A34004_DPLL-2
R3 R8 = CMP-2002-06458-1: Part Number: ERJ-U02F1000X; Manufacturer: Panasonic
R7 R26 = CMP-2002-04448-1: Part Number: RK73H1ETTP49R9F; Manufacturer: KOA Speer
R27-R29 R95 R96 = CMP-2002-05217-1: as R18 on sheet 02-8A34004_DPLL-1
Y1 = CMP-25159-259584-1: MEMS OSC TCXO 40.0000MHZ LVCMOS; Frequency Stability: 5ppm; Max Supply Current: 33mA; Frequency: 40MHz
Y4 = CMP-OSC-00029-2: OSC, MEMS, STRATUM 3E, 10.000MHZ, 10PPB STAB, LVCMOS, 3.3V, O/P EN, 7.0X5.0X2.2MM, CQFN-10; Manufacturer Part Number: SiT5501AI-WU033JH-10.000000; Manufacturer: SiTime; Frequency: 10 MHz

## Sheet 05-USB-Prog.SchDoc
size B; SheetNumber: 5; SheetTotal: 8
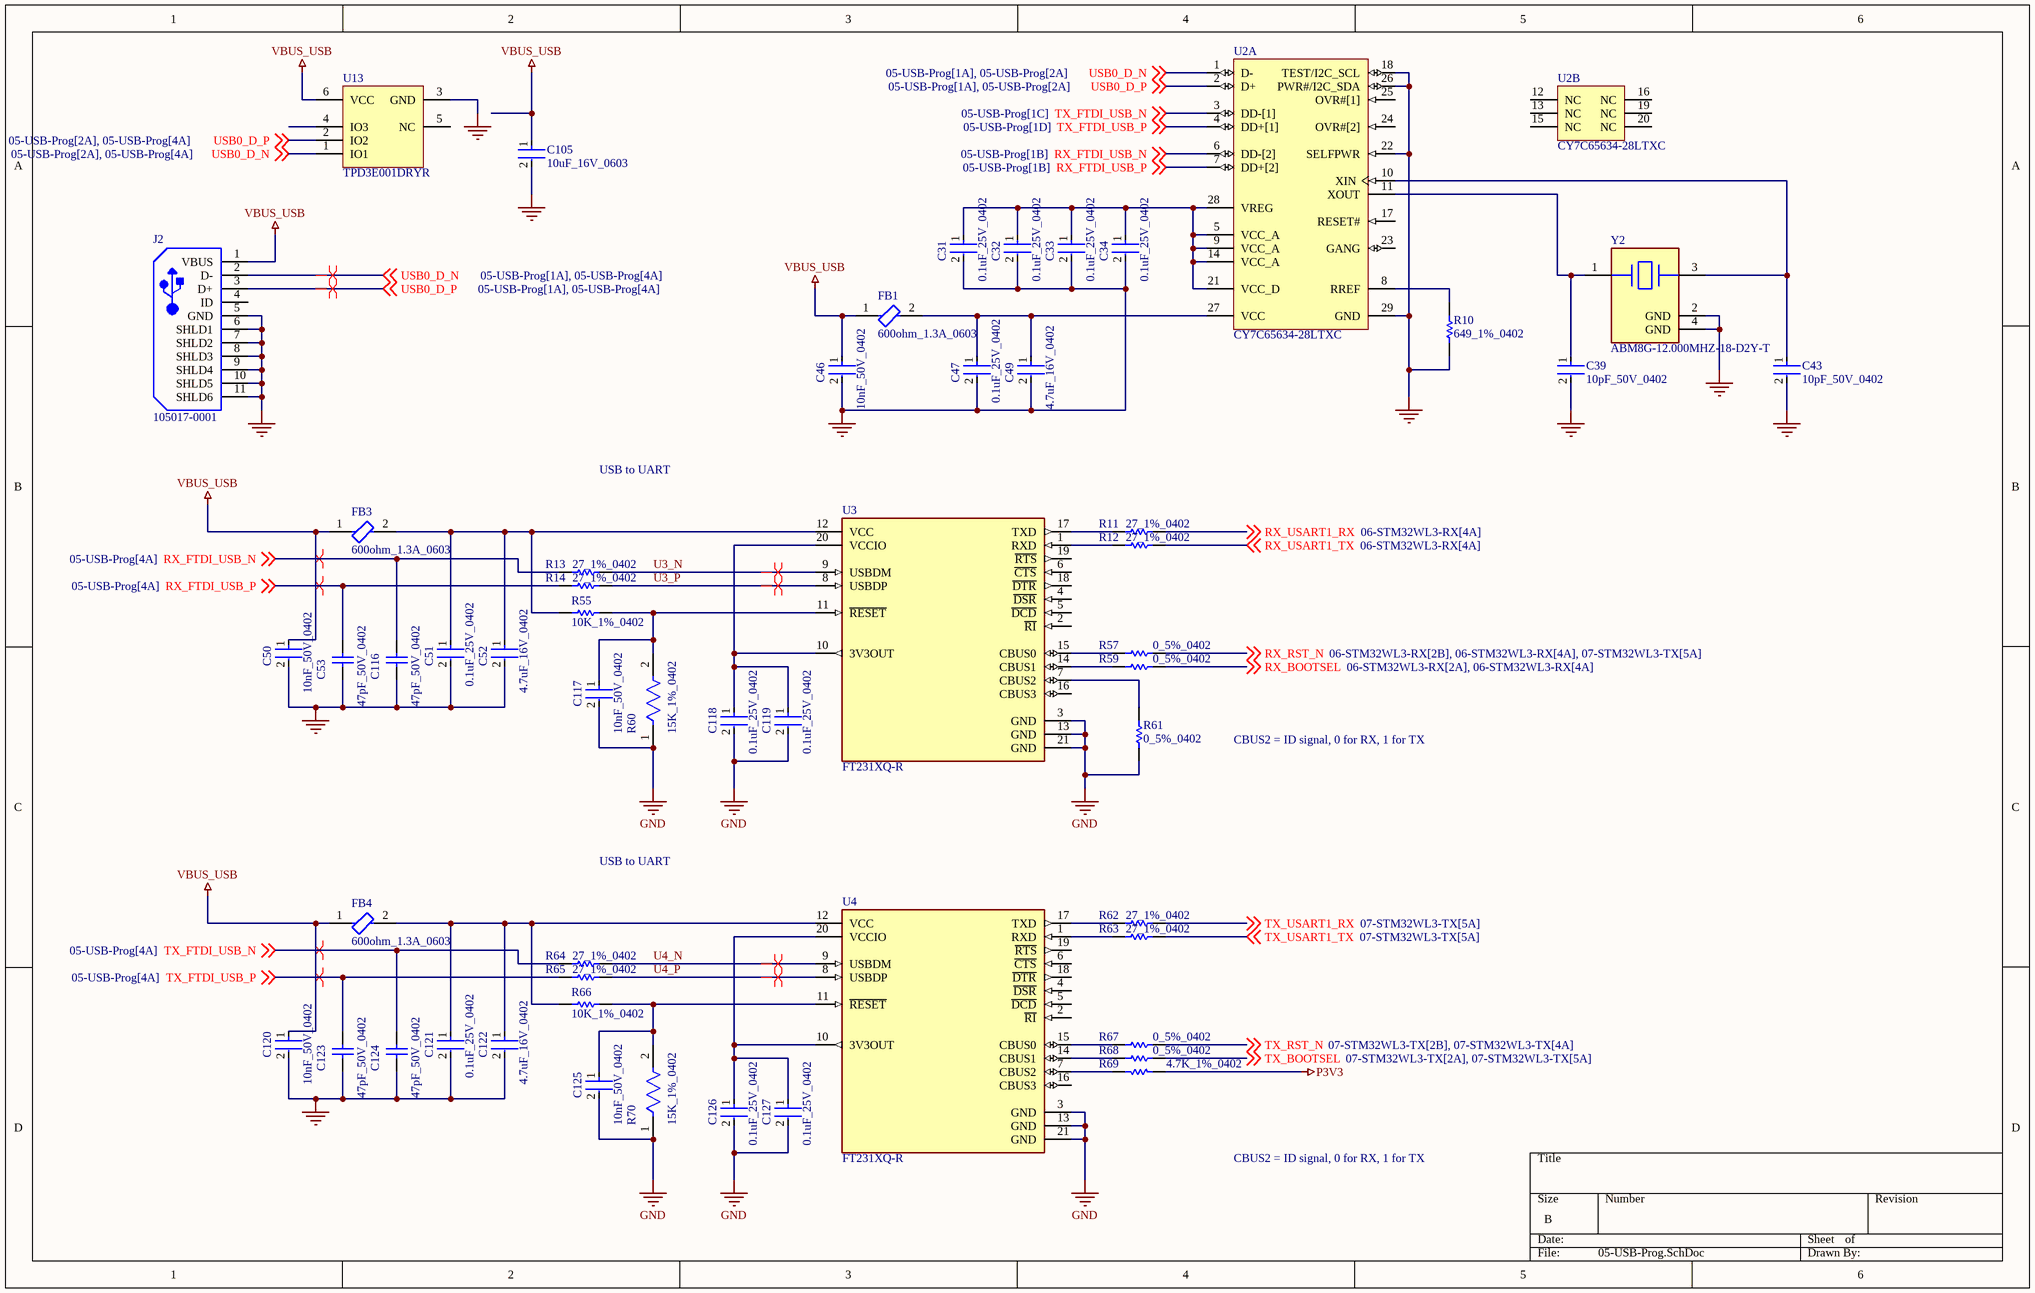
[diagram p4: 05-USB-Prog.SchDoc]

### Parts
C31  0.1uF_25V_0402  [FP-0402-L_1_0_1-W_0_5_0_1-IPC_C]
C32  0.1uF_25V_0402  [FP-0402-L_1_0_1-W_0_5_0_1-IPC_C]
C33  0.1uF_25V_0402  [FP-0402-L_1_0_1-W_0_5_0_1-IPC_C]
C34  0.1uF_25V_0402  [FP-0402-L_1_0_1-W_0_5_0_1-IPC_C]
C39  10pF_50V_0402  [FP-C1005-050-0_05-IPC_C]
C43  10pF_50V_0402  [FP-C1005-050-0_05-IPC_C]
C46  10nF_50V_0402  [FP-CC0402-MFG]
C47  0.1uF_25V_0402  [FP-0402-L_1_0_1-W_0_5_0_1-IPC_C]
C49  4.7uF_16V_0402  [FP-CL829-IPC_C]
C50  10nF_50V_0402  [FP-CC0402-MFG]
C51  0.1uF_25V_0402  [FP-0402-L_1_0_1-W_0_5_0_1-IPC_C]
C52  4.7uF_16V_0402  [FP-CL829-IPC_C]
C53  47pF_50V_0402  [CAPC1005X55X25LL05T10]
C105  10uF_16V_0603  [FP-0603-L_1_6_0_2-W_0_8_0-MFG]
C116  47pF_50V_0402  [CAPC1005X55X25LL05T10]
C117  10nF_50V_0402  [FP-CC0402-MFG]
C118  0.1uF_25V_0402  [FP-0402-L_1_0_1-W_0_5_0_1-IPC_C]
C119  0.1uF_25V_0402  [FP-0402-L_1_0_1-W_0_5_0_1-IPC_C]
C120  10nF_50V_0402  [FP-CC0402-MFG]
C121  0.1uF_25V_0402  [FP-0402-L_1_0_1-W_0_5_0_1-IPC_C]
C122  4.7uF_16V_0402  [FP-CL829-IPC_C]
C123  47pF_50V_0402  [CAPC1005X55X25LL05T10]
C124  47pF_50V_0402  [CAPC1005X55X25LL05T10]
C125  10nF_50V_0402  [FP-CC0402-MFG]
C126  0.1uF_25V_0402  [FP-0402-L_1_0_1-W_0_5_0_1-IPC_C]
C127  0.1uF_25V_0402  [FP-0402-L_1_0_1-W_0_5_0_1-IPC_C]
FB1  600ohm_1.3A_0603  [FP-BLM18-0_15-t0_8-IPC_A]
FB3  600ohm_1.3A_0603  [FP-BLM18-0_15-t0_8-IPC_A]
FB4  600ohm_1.3A_0603  [FP-BLM18-0_15-t0_8-IPC_A]
J2  105017-0001  [USB-MICRO-B_V]
R10  649_1%_0402  [RESC1005X40X25LL05T05]
R11  27_1%_0402  [RESC1005X40X25NL05T05]
R12  27_1%_0402  [RESC1005X40X25NL05T05]
R13  27_1%_0402  [RESC1005X40X25NL05T05]
R14  27_1%_0402  [RESC1005X40X25NL05T05]
R55  10K_1%_0402  [RESC1005X40X25LL05T10]
R57  0_5%_0402  [RESC1005X40X25NL05T10]
R59  0_5%_0402  [RESC1005X40X25NL05T10]
R60  15K_1%_0402  [FP-ERJ2R-MFG]
R61  0_5%_0402  [RESC1005X40X25NL05T10]
R62  27_1%_0402  [RESC1005X40X25NL05T05]
R63  27_1%_0402  [RESC1005X40X25NL05T05]
R64  27_1%_0402  [RESC1005X40X25NL05T05]
R65  27_1%_0402  [RESC1005X40X25NL05T05]
R66  10K_1%_0402  [RESC1005X40X25LL05T10]
R67  0_5%_0402  [RESC1005X40X25NL05T10]
R68  0_5%_0402  [RESC1005X40X25NL05T10]
R69  4.7K_1%_0402  [RESC1005X40X25NL10T10]
R70  15K_1%_0402  [FP-ERJ2R-MFG]
U2  CY7C65634-28LTXC  [CYP-LTX28_M]  (parts A,B of 2)
U3  FT231XQ-R  [FP-QFN-20-MFG]
U4  FT231XQ-R  [FP-QFN-20-MFG]
U13  TPD3E001DRYR  [DRY0006A]
Y2  ABM8G-12.000MHZ-18-D2Y-T  [FP-ABM8G-MFG]

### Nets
GND: C31.2 C32.2 C33.2 C34.2 C39.2 C43.2 C46.2 C47.2 C49.2 C50.2 C51.2 C52.2 C53.1 C105.2 C116.1 C117.2 C118.2 C119.2 C120.2 C121.2 C122.2 C123.1 C124.1 C125.2 C126.2 C127.2 J2.5(GND) J2.6(SHLD1) J2.7(SHLD2) J2.8(SHLD3) J2.9(SHLD4) J2.10(SHLD5) J2.11(SHLD6) R10.1 R60.1 R61.1 R70.1 U2.18(TEST/I2C_SCL) U2.22(SELFPWR) U2.26(PWR#/I2C_SDA) U2.29(GND) U3.3(GND) U3.13(GND) U3.21(GND) U4.3(GND) U4.13(GND) U4.21(GND) U13.3(GND) Y2.2(GND) Y2.4(GND)
P3V3: R69.1
VBUS_USB: C46.1 C50.1 C105.1 C120.1 FB1.1 FB3.1 FB4.1 J2.1(VBUS) U13.6(VCC)
RX_BOOTSEL: R59.2 ; off-sheet RX_BOOTSEL
RX_FTDI_USB_N: C116.2 R13.1 U2.6(DD-[2]) ; off-sheet RX_FTDI_USB_N
RX_FTDI_USB_P: C53.2 R14.1 U2.7(DD+[2]) ; off-sheet RX_FTDI_USB_P
RX_RST_N: R57.2 ; off-sheet RX_RST_N
RX_USART1_RX: R11.2 ; off-sheet RX_USART1_RX
RX_USART1_TX: R12.2 ; off-sheet RX_USART1_TX
TX_BOOTSEL: R68.2 ; off-sheet TX_BOOTSEL
TX_FTDI_USB_N: C124.2 R64.1 U2.3(DD-[1]) ; off-sheet TX_FTDI_USB_N
TX_FTDI_USB_P: C123.2 R65.1 U2.4(DD+[1]) ; off-sheet TX_FTDI_USB_P
TX_RST_N: R67.2 ; off-sheet TX_RST_N
TX_USART1_RX: R62.2 ; off-sheet TX_USART1_RX
TX_USART1_TX: R63.2 ; off-sheet TX_USART1_TX
U3_N: R13.2 U3.9(USBDM)
U3_P: R14.2 U3.8(USBDP)
U4_N: R64.2 U4.9(USBDM)
U4_P: R65.2 U4.8(USBDP)
USB0_D_N: J2.2(D-) U2.1(D-) U13.1(IO1) ; off-sheet USB0_D_N
USB0_D_P: J2.3(D+) U2.2(D+) U13.2(IO2) ; off-sheet USB0_D_P
NetC31_1: C31.1 C32.1 C33.1 C34.1 U2.5(VCC_A) U2.9(VCC_A) U2.14(VCC_A) U2.21(VCC_D) U2.28(VREG)
NetC39_1: C39.1 U2.11(XOUT) Y2.1
NetC43_1: C43.1 U2.10(XIN) Y2.3
NetC47_1: C47.1 C49.1 FB1.2 U2.27(VCC)
NetC51_1: C51.1 C52.1 FB3.2 R55.2 U3.12(VCC)
NetC117_1: C117.1 R55.1 R60.2 U3.11(~{RESET})
NetC118_1: C118.1 C119.1 U3.10(3V3OUT) U3.20(VCCIO)
NetC121_1: C121.1 C122.1 FB4.2 R66.2 U4.12(VCC)
NetC125_1: C125.1 R66.1 R70.2 U4.11(~{RESET})
NetC126_1: C126.1 C127.1 U4.10(3V3OUT) U4.20(VCCIO)
NetR10_2: R10.2 U2.8(RREF)
NetR11_1: R11.1 U3.17(TXD)
NetR12_1: R12.1 U3.1(RXD)
NetR57_1: R57.1 U3.15(CBUS0)
NetR59_1: R59.1 U3.14(CBUS1)
NetR61_2: R61.2 U3.7(CBUS2)
NetR62_1: R62.1 U4.17(TXD)
NetR63_1: R63.1 U4.1(RXD)
NetR67_1: R67.1 U4.15(CBUS0)
NetR68_1: R68.1 U4.14(CBUS1)
NetR69_2: R69.2 U4.7(CBUS2)

Not connected (* = marked no-connect by the designer): J2 4(ID); U2 12(NC) 13(NC) 15(NC) 16(NC) 17(RESET#) 19(NC) 20(NC) 23(GANG) 24(OVR#[2]) 25(OVR#[1]); U3 2(~{RI}) 4(~{DSR}) 5(~{DCD}) 6(~{CTS}) 16(CBUS3) 18(~{DTR}) 19(~{RTS}); U4 2(~{RI}) 4(~{DSR}) 5(~{DCD}) 6(~{CTS}) 16(CBUS3) 18(~{DTR}) 19(~{RTS}); U13 4(IO3) 5(NC)

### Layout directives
differential pair: RX_FTDI_USB_N, RX_FTDI_USB_P, TX_FTDI_USB_N, TX_FTDI_USB_P, U3_N, U3_P, U4_N, U4_P, USB0_D_N, USB0_D_P

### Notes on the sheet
- USB to UART
- CBUS2 = ID signal, 0 for RX, 1 for TX

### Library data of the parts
C31-C34 C47 C51 C118 C119 C121 C126 C127 = CMP-2008-02519-2: as C2 on sheet 01-Antennas
C39 C43 = CMP-08246-002674-1: CAP CER 10PF 50V C0G 0402; Temperature Coefficient: 30ppm/°C; Dielectric Material: Ceramic
C46 C50 C117 C120 C125 = CMP-2100-03592-2: CAP CER 10000PF 50V X7R 0402; Manufacturer Part Number: CC0402KRX7R9BB103; Manufacturer: YAGEO; Temperature Coefficient: 30ppm/°C; Capacitance: 10 nF; Material: Ceramic; Automotive Grade: NA; Tolerance: 0.1; Value: 10 nF
C49 C52 C122 = CMP-13271-001468-1: Cap Ceramic 4.7uF 16V X5R ±20% SMD 0402 +85°C Paper T/R
C53 C116 C123 C124 = CMP-2008-04368-1: Part Number: GRM1555C1H470JA01D; Manufacturer: Murata
C105 = CMP-2000-06226-4: Multilayer Ceramic Capacitor 10uF 16V X5R 20% SMD 0603 T/R
FB1 FB3 FB4 = CMP-0686-00581-3: Chip Ferrite Bead, 0603, 600Ω @ 100MHz, 0.15Ω, 25%, 1.3A; Material: Steel; Number of Lines: 1; Impedance: 600R; DC Resistance (DCR): 150mR
J2 = CMP-2000-05827-1: Micro-USB B Receptacle, Right Angle, Bottom Mount, Surface Mount, with Solder Tabs, -30 to 85 degC, 5-Pin USB, RoHS, Tape and Reel; Manufacturer: Molex; Featured Product: Micro-USBConnectorsUSBConnectors; Other Names: WM1399DKR; Package Version: Rev. F, 12/2012; Number of Contacts: 5; Connector Type: USB-microB; Catalog Drawings: 1050170001; 3D Model: 105017-0001.stp; Mating Products: WM17145-ND-CABLEMICROUSBBTOSTDA1.0MWM17147-ND-CABLEMICROUSBBTOSTDA2.0MWM17146-ND-CABLEMICROUSBBTOSTDA1.5M; PCN Assembly/Origin: ResinSupplier21/Oct/2015; Voltage - Max: 30V; Online Catalog: Molex-MicroUSB
R10 = CMP-2002-01027-1: Part Number: ERJ-2RKF6490X; Manufacturer: Panasonic
R11-R14 R62-R65 = CMP-2002-08434-1: Part Number: CRCW040227R0FKED; Manufacturer: Vishay Dale
R55 R66 = CMP-2002-07353-1: Part Number: RC0402FR-0710KL; Manufacturer: Yageo / Phycomp
R57 R59 R61 R67 R68 = CMP-2002-06457-1: as R1 on sheet 01-Antennas
R60 R70 = CMP-2002-00694-4: RES SMD 15K OHM 1% 1/10W 0402; Manufacturer Part Number: ERJ-2RKF1502X; Manufacturer: Panasonic; Automotive Grade: Grade 0; Voltage Rating: 50V; Resistance: 15kΩ; Temperature Coefficient: 100ppm/°C; Power Rating: 0.1W; Value: 15kΩ
R69 = CMP-2002-05217-1: as R18 on sheet 02-8A34004_DPLL-1
U2 = CMP-0967-00085-1: HX2VL(TM) Very Low Power USB 2.0 Hub Controller, 2 Hub Ports, 0 to 70 degC, 28-Pin QFN (LTX28), Bulk; Manufacturer: Cypress; No. of Hub Ports: 2; Max. Operating Voltage (V): 5.25; Single/Multi TT: Single; Min. Operating Voltage (V): 3.15
U3 U4 = CMP-0248-00001-3: IC USB SERIAL FULL UART 20QFN; Data Rate: 12Mbps; Operating Supply Current: 8mA; Min Supply Voltage: 2.97V; Max Supply Voltage: 5.5V; Number of Channels: 1
U13 = CMP-0326-00032-3: Low-Capacitance + / - 15 kV ESD-Protection Array for High-Speed Data Interfaces, 3 Channels, -40 to +85 degC, 6-pin SON (DRY), Green (RoHS & no Sb/Br); Manufacturer: Texas Instruments; USB High Speed: TRUE; SubFamily: ESD Solution; IO Capacitance(Typ)(pF): 1.5; IEC 61000-4-2 Contact(+/- kV): 8; IO Leakage Current(nA): Jan-00; Breakdown Voltage(Min)(V): 11; IEC 61000-4-2 Air-Gap(+/- kV): 15
Y2 = CMP-2000-05039-3: Crystal 12MHz ±20ppm (Tol) ±30ppm (Stability) 18pF FUND 120Ω 4-Pin SMD T/R; Series Resistance: 120R

## Sheet 06-STM32WL3-RX.SchDoc
size B; SheetNumber: 6; SheetTotal: 8
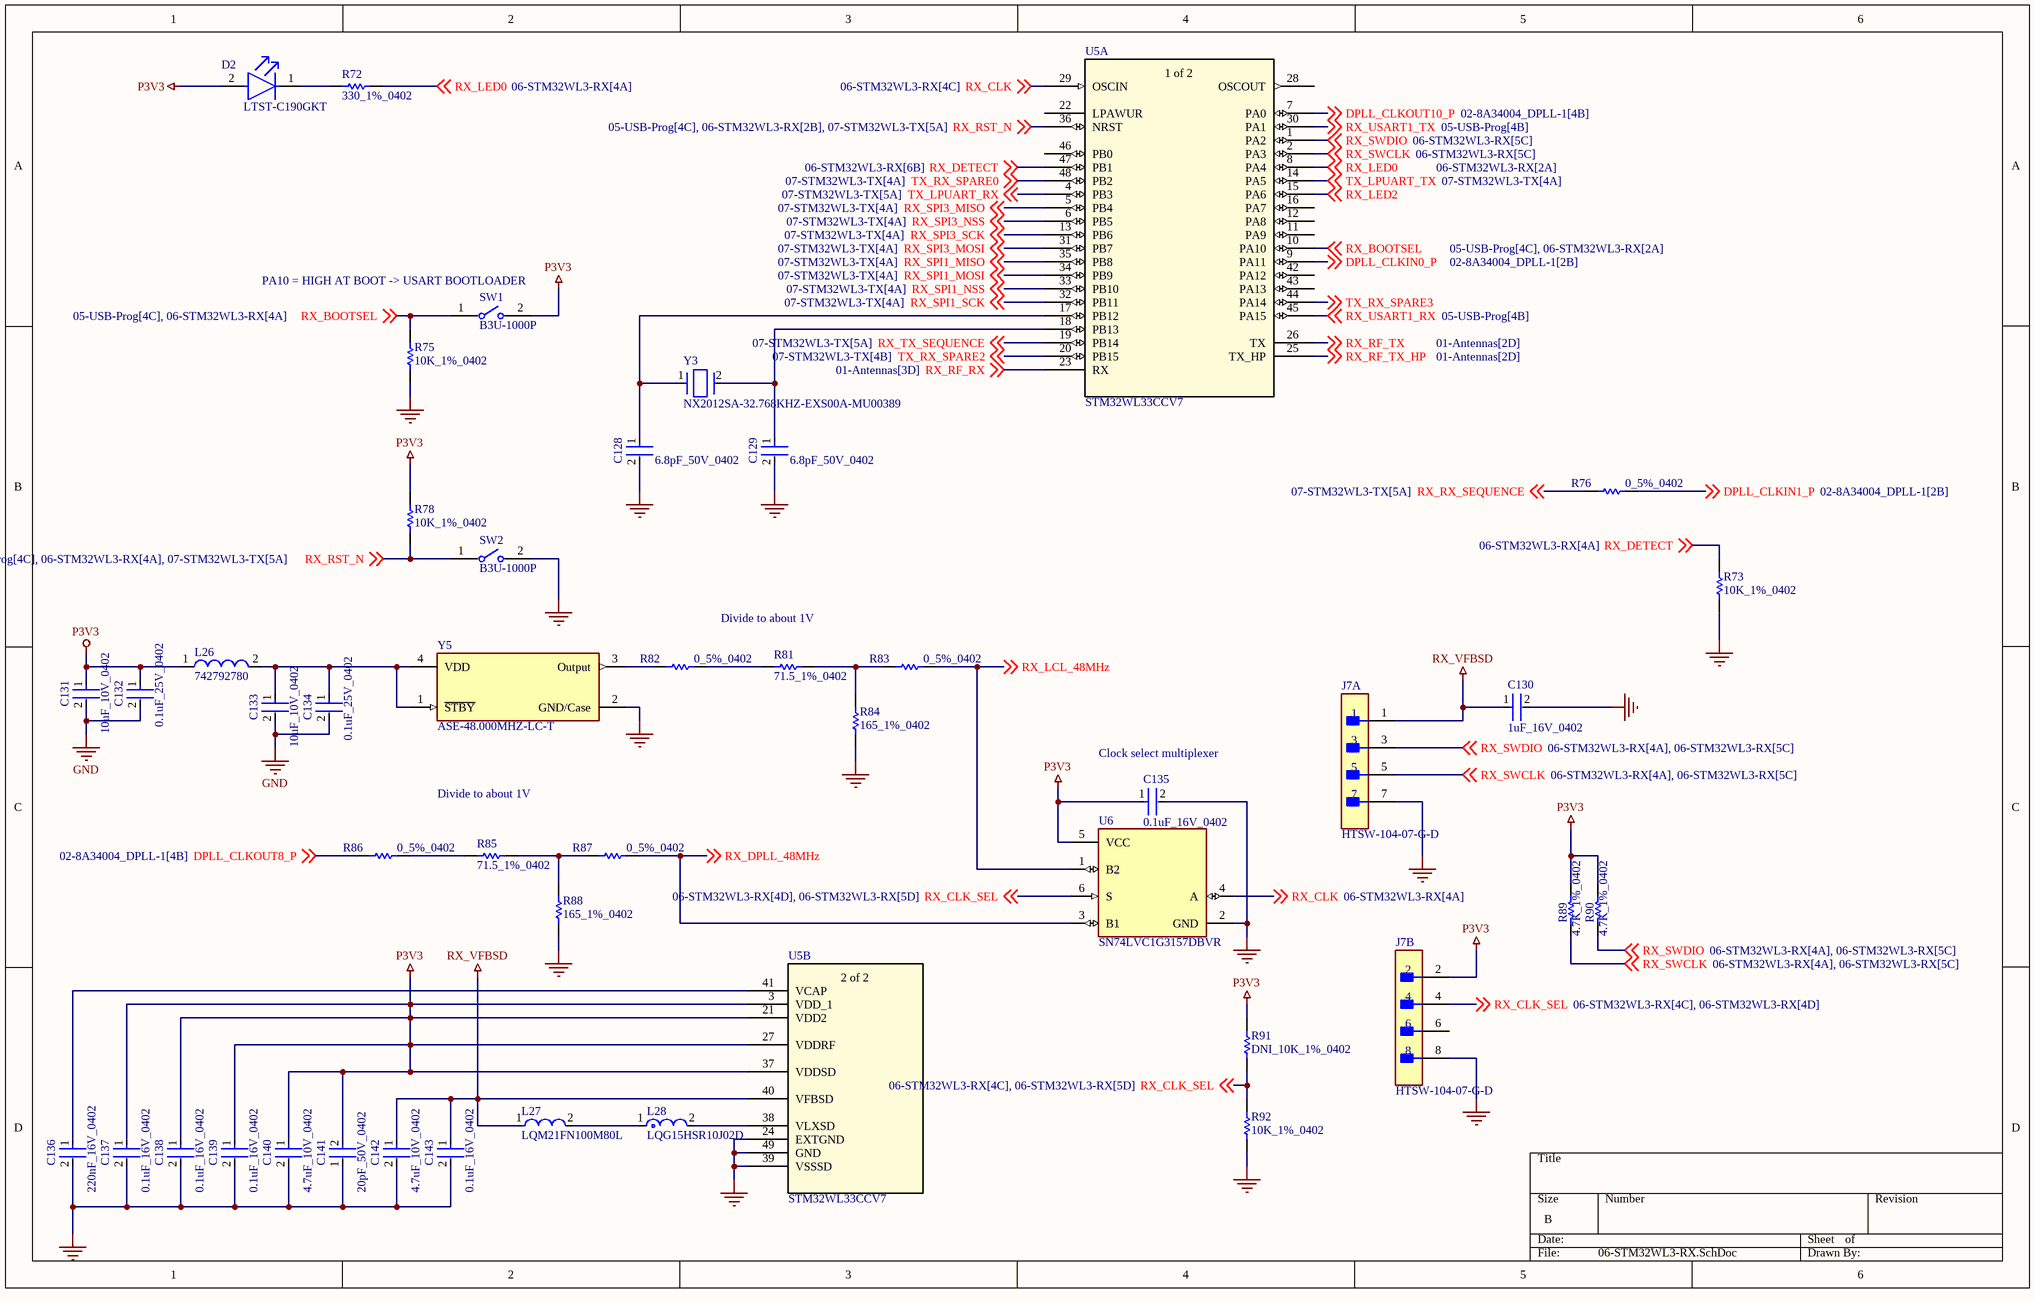
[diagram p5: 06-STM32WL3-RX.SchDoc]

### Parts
C128  6.8pF_50V_0402  [FP-GJM155-0_05-IPC_A]
C129  6.8pF_50V_0402  [FP-GJM155-0_05-IPC_A]
C130  1uF_16V_0402  [FP-0402-L_1_0_0_05-W_0_5-IPC_A]
C131  10uF_10V_0402  [FP-CL05A106MP5NUNC-MFG]
C132  0.1uF_25V_0402  [FP-0402-L_1_0_1-W_0_5_0_1-IPC_C]
C133  10uF_10V_0402  [FP-CL05A106MP5NUNC-MFG]
C134  0.1uF_25V_0402  [FP-0402-L_1_0_1-W_0_5_0_1-IPC_C]
C135  0.1uF_16V_0402  [FP-C0402-BB-MFG]
C136  220nF_16V_0402  [FP-GRM155-0_05-IPC_C]
C137  0.1uF_16V_0402  [FP-C0402-BB-MFG]
C138  0.1uF_16V_0402  [FP-C0402-BB-MFG]
C139  0.1uF_16V_0402  [FP-C0402-BB-MFG]
C140  4.7uF_10V_0402  [FP-C1005-050-0_15-MFG]
C141  20pF_50V_0402  [FP-CBR04C-MFG]
C142  4.7uF_10V_0402  [FP-C1005-050-0_15-MFG]
C143  0.1uF_16V_0402  [FP-C0402-BB-MFG]
D2  LTST-C190GKT  [FP-LTST-C190GKT-MFG]
J7  HTSW-104-07-G-D  [FP-HTSW-104-07-G-D-MFG]  (parts A,B of 2)
L26  742792780  [SMD-0402]
L27  LQM21FN100M80L  [FP-LQM21DH_70-IPC_C]
L28  LQG15HSR10J02D  [FP-LQG15HH_02-IPC_A]
R72  330_1%_0402  [RESC1005X40X25NL10T10]
R73  10K_1%_0402  [RESC1005X40X25NL10T10]
R75  10K_1%_0402  [RESC1005X40X25NL10T10]
R76  0_5%_0402  [RESC1005X40X25NL05T10]
R78  10K_1%_0402  [RESC1005X40X25NL10T10]
R81  71.5_1%_0402  [RESC1005X40X25NL05T05]
R82  0_5%_0402  [RESC1005X40X25NL05T10]
R83  0_5%_0402  [RESC1005X40X25NL05T10]
R84  165_1%_0402  [RESC1005X40X25NL05T05]
R85  71.5_1%_0402  [RESC1005X40X25NL05T05]
R86  0_5%_0402  [RESC1005X40X25NL05T10]
R87  0_5%_0402  [RESC1005X40X25NL05T10]
R88  165_1%_0402  [RESC1005X40X25NL05T05]
R89  4.7K_1%_0402  [RESC1005X40X25NL10T10]
R90  4.7K_1%_0402  [RESC1005X40X25NL10T10]
R91  DNI_10K_1%_0402  [RESC1005X40X25NL10T10]  (no BOM)
R92  10K_1%_0402  [RESC1005X40X25NL10T10]
SW1  B3U-1000P  [FP-B3U-1000P-MFG]
SW2  B3U-1000P  [FP-B3U-1000P-MFG]
U5  STM32WL33CCV7  [UFQFPN-48_STM]  (parts A,B of 2)
U6  SN74LVC1G3157DBVR  [FP-DBV0006A-IPC_C]
Y3  NX2012SA-32.768KHZ-EXS00A-MU00389  [FP-NX2012SA-MFG]
Y5  ASE-48.000MHZ-LC-T  [FP-ASE-MFG]

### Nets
GND: C128.2 C129.2 C130.2 C131.2 C132.2 C133.2 C134.2 C135.2 C136.2 C137.2 C138.2 C139.2 C140.2 C141.1 C142.2 C143.2 J7.7 J7.8 R73.2 R75.2 R84.1 R88.1 R92.2 SW2.2 U5.24(EXTGND) U5.39(VSSSD) U5.49(GND) U6.2(GND) Y5.2(GND/Case)
P3V3: C131.1 C132.1 C135.1 C137.1 C138.1 C139.1 C140.1 C141.2 D2.2(A) J7.2 L26.1 R78.1 R89.2 R90.2 R91.1 SW1.2 U5.3(VDD_1) U5.21(VDD2) U5.27(VDDRF) U5.37(VDDSD) U6.5(VCC)
RX_VFBSD: C130.1 C142.1 C143.1 J7.1 L27.1 U5.40(VFBSD)
DPLL_CLKIN0_P: U5.9(PA11) ; off-sheet DPLL_CLKIN0_P
DPLL_CLKIN1_P: R76.2 ; off-sheet DPLL_CLKIN1_P
DPLL_CLKOUT8_P: R86.1 ; off-sheet DPLL_CLKOUT8_P
DPLL_CLKOUT10_P: U5.7(PA0) ; off-sheet DPLL_CLKOUT10_P
RX_BOOTSEL: R75.1 SW1.1 U5.10(PA10) ; off-sheet RX_BOOTSEL
RX_CLK: U5.29(OSCIN) U6.4(A) ; off-sheet RX_CLK
RX_CLK_SEL: J7.4 R91.2 R92.1 U6.6(S) ; off-sheet RX_CLK_SEL
RX_DETECT: R73.1 U5.47(PB1) ; off-sheet RX_DETECT
RX_DPLL_48MHz: R87.2 U6.3(B1) ; off-sheet RX_DPLL_48MHz
RX_LCL_48MHz: R83.2 U6.1(B2) ; off-sheet RX_LCL_48MHz
RX_LED0: R72.1 U5.8(PA4) ; off-sheet RX_LED0
RX_LED2: U5.15(PA6) ; off-sheet RX_LED2
RX_RF_RX: U5.23(RX) ; off-sheet RX_RF_RX
RX_RF_TX: U5.26(TX) ; off-sheet RX_RF_TX
RX_RF_TX_HP: U5.25(TX_HP) ; off-sheet RX_RF_TX_HP
RX_RST_N: R78.2 SW2.1 U5.36(NRST) ; off-sheet RX_RST_N
RX_RX_SEQUENCE: R76.1 ; off-sheet RX_RX_SEQUENCE
RX_SPI1_MISO: U5.35(PB8) ; off-sheet RX_SPI1_MISO
RX_SPI1_MOSI: U5.34(PB9) ; off-sheet RX_SPI1_MOSI
RX_SPI1_NSS: U5.33(PB10) ; off-sheet RX_SPI1_NSS
RX_SPI1_SCK: U5.32(PB11) ; off-sheet RX_SPI1_SCK
RX_SPI3_MISO: U5.5(PB4) ; off-sheet RX_SPI3_MISO
RX_SPI3_MOSI: U5.31(PB7) ; off-sheet RX_SPI3_MOSI
RX_SPI3_NSS: U5.6(PB5) ; off-sheet RX_SPI3_NSS
RX_SPI3_SCK: U5.13(PB6) ; off-sheet RX_SPI3_SCK
RX_SWCLK: J7.5 R89.1 U5.2(PA3) ; off-sheet RX_SWCLK
RX_SWDIO: J7.3 R90.1 U5.1(PA2) ; off-sheet RX_SWDIO
RX_TX_SEQUENCE: U5.19(PB14) ; off-sheet RX_TX_SEQUENCE
RX_USART1_RX: U5.45(PA15) ; off-sheet RX_USART1_RX
RX_USART1_TX: U5.30(PA1) ; off-sheet RX_USART1_TX
TX_LPUART_RX: U5.4(PB3) ; off-sheet TX_LPUART_RX
TX_LPUART_TX: U5.14(PA5) ; off-sheet TX_LPUART_TX
TX_RX_SPARE0: U5.48(PB2) ; off-sheet TX_RX_SPARE0
TX_RX_SPARE2: U5.20(PB15) ; off-sheet TX_RX_SPARE2
TX_RX_SPARE3: U5.44(PA14) ; off-sheet TX_RX_SPARE3
NetC128_1: C128.1 U5.17(PB12) Y3.1
NetC129_1: C129.1 U5.18(PB13) Y3.2
NetC133_1: C133.1 C134.1 L26.2 Y5.1(~{STBY}) Y5.4(VDD)
NetC136_1: C136.1 U5.41(VCAP)
NetD2_1: D2.1(C) R72.2
NetL27_2: L27.2 L28.1
NetL28_2: L28.2 U5.38(VLXSD)
NetR81_1: R81.1 R82.2
NetR81_2: R81.2 R83.1 R84.2
NetR82_1: R82.1 Y5.3(Output)
NetR85_1: R85.1 R86.2
NetR85_2: R85.2 R87.1 R88.2

Not connected (* = marked no-connect by the designer): J7 6; U5 11(PA9) 12(PA8) 16(PA7) 22(LPAWUR) 28(OSCOUT) 42(PA12) 43(PA13) 46(PB0)

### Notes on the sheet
- (near SW1) PA10 = HIGH AT BOOT -> USART BOOTLOADER
- Divide to about 1V
- (near C135) Clock select multiplexer

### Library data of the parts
C128 C129 = CMP-2008-03875-2: Multi-Layer Ceramic Capacitor 6.8pF C0G  ±0.25pF 0402 Paper T/R; Voltage: 50V
C130 = CMP-14477-000104-2: None; Tolerance: 10%; Voltage Rating: 16V; Dielectric: X5R; Capacitance: 1uF
C131 C133 = CMP-13271-000002-1: as C58 on sheet 02-8A34004_DPLL-1
C132 C134 = CMP-2008-02519-2: as C2 on sheet 01-Antennas
C135 C137-C139 C143 = CMP-1034-02068-3: as C11 on sheet 01-Antennas
C136 = CMP-1034-02089-3: Chip Multilayer Ceramic Capacitors for General Purpose, 0402, 0.22uF, X7R, 15%, 10%, 16V; Capacitance: 220nF
C140 C142 = CMP-2000-05997-2: CAP CER 4.7UF 10V X5R 0402; Dielectric Material: Ceramic; Tolerance: 10%
C141 = CMP-2008-00009-2: CAP CER 20PF 50V C0G/NP0 0402; Manufacturer: KEMET; Manufacturer Part Number: CBR04C200J5GAC; Temperature Coefficient: 30ppm/°C; Material: Ceramic; Tolerance: 0.05; Temperature Characteristic: C0G
D2 = CMP-22017-000005-2: as D1 on sheet 02-8A34004_DPLL-1
J7 = CMP-02766-000066-1: CONN HEADER VERT 8POS 2.54MM; Manufacturer: Samtec; Conn Orientation: Straight; Voltage Rating: 550V; Current Rating: 6.3A; Number Of Contacts: 8; Conn Gender: Male
L26 = CMP-0220-00137-1: as L3 on sheet 03-8A34004_DPLL-2
L27 = CMP-06042-014493-1: Multilayer Type Inductor for Power Lines, 0805 (2012), 10μH, 20%, 0.39Ω, 100mA; Self Resonant Frequency: 15MHz; Test Frequency: 1MHz; DC Resistance (DCR): 300mR; Shielding: Shielded; Core Material: Ferrite; Inductance: 10uH
L28 = CMP-06042-015241-1: Multilayer type RF Inductor 100nH ±5% 1.25Ω 200mA 0402; Q Factor: 8; Shielding: Unshielded; Max DC Current: 150mA; Core Material: Air; Self Resonant Frequency: 600MHz; DC Resistance (DCR): 1.25R; Test Frequency: 100MHz
R72 = CMP-2002-05853-1: as R71 on sheet 02-8A34004_DPLL-1
R73 R75 R78 R91 R92 = CMP-2002-04694-1: Manufacturer: Bourns; Part Number: CR0402-FX-1002GLF
R76 R82 R83 R86 R87 = CMP-2002-06457-1: as R1 on sheet 01-Antennas
R81 R85 = CMP-2002-00202-1: Manufacturer: Vishay Dale; Part Number: CRCW040271R5FKED
R84 R88 = CMP-2002-08233-1: Manufacturer: Vishay Dale; Part Number: CRCW0402165RFKED
R89 R90 = CMP-2002-05217-1: as R18 on sheet 02-8A34004_DPLL-1
SW1 SW2 = CMP-2100-03586-2: SWITCH TACTILE SPST-NO 0.05A 12V; Contact Resistance: 100mR; Operating Force: 1.5N; Max Current Rating: 50mA; Switch Travel: 0.15mm; Actuator Type: Standard; Mechanical Life: 200000Cycles; Ratings: Dust Proof; Illumination Type: Non-Illuminated; Throw Configuration: SPST; Actuator Length: 0.4mm; Switch Function: Off-Mom
U5 = STM32WL33CCV7: No Description Available; Mfr_Name: STMicroelectronics
U6 = CMP-0859-00203-4: IC SWITCH SPDT SOT23-6; Number of Outputs: 2; Propagation Delay: 300ps; On-State Resistance: 15R; Nominal Supply Current: 10uA; Number of Inputs: 1; Max Supply Voltage: 5.5V; Supply Type: Single; Low Level Output Current: 128mA; Bandwidth: 300MHz; Turn-Off Delay Time: 3.8ns; Turn-On Delay Time: 5.7ns; Operating Supply Current: 1uA; Min Supply Voltage: 1.65V; Polarity: Non-Inverting
Y3 = CMP-200220-000005-1: CRYSTAL 32.768KHZ 7PF SMD; Manufacturer: NDK America; Esr: 80kΩ; Load Capacitance: 12.5pF; Tolerance: 20ppm
Y5 = CMP-27762-000273-1: XTAL Oscillator 48MHz ±50ppm CMOS 3.3V 4-SMD 3.2mm x 2.5mm; Min Supply Voltage: 3.135V; Max Supply Voltage: 3.465V; Load Capacitance: 15pF; Max Supply Current: 19mA

## Sheet 07-STM32WL3-TX.SchDoc
size B; SheetNumber: 7; SheetTotal: 8
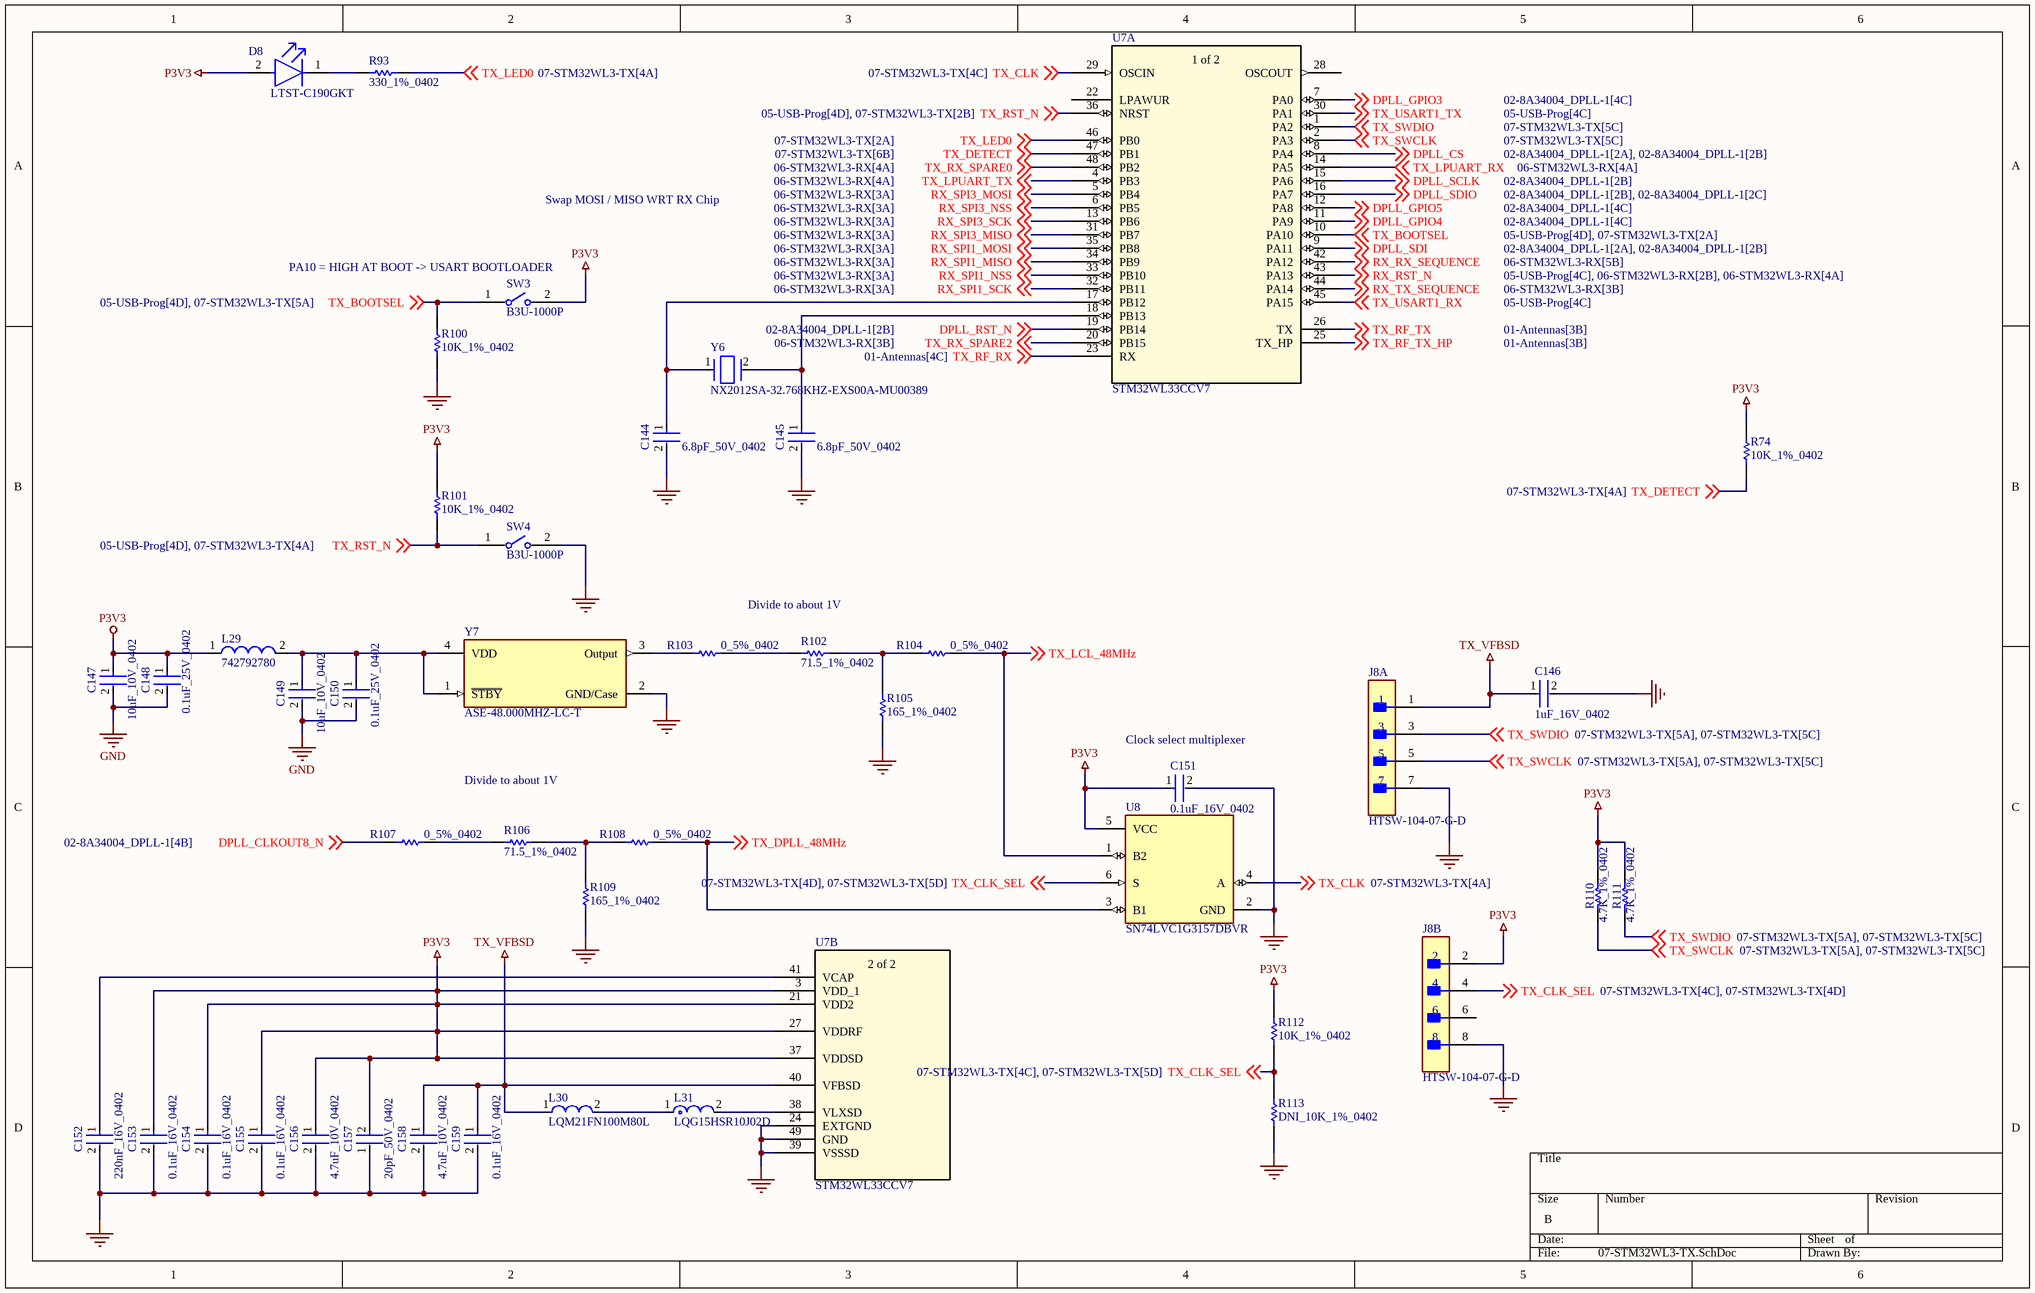
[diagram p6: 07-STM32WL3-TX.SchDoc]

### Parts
C144  6.8pF_50V_0402  [FP-GJM155-0_05-IPC_A]
C145  6.8pF_50V_0402  [FP-GJM155-0_05-IPC_A]
C146  1uF_16V_0402  [FP-0402-L_1_0_0_05-W_0_5-IPC_A]
C147  10uF_10V_0402  [FP-CL05A106MP5NUNC-MFG]
C148  0.1uF_25V_0402  [FP-0402-L_1_0_1-W_0_5_0_1-IPC_C]
C149  10uF_10V_0402  [FP-CL05A106MP5NUNC-MFG]
C150  0.1uF_25V_0402  [FP-0402-L_1_0_1-W_0_5_0_1-IPC_C]
C151  0.1uF_16V_0402  [FP-C0402-BB-MFG]
C152  220nF_16V_0402  [FP-GRM155-0_05-IPC_C]
C153  0.1uF_16V_0402  [FP-C0402-BB-MFG]
C154  0.1uF_16V_0402  [FP-C0402-BB-MFG]
C155  0.1uF_16V_0402  [FP-C0402-BB-MFG]
C156  4.7uF_10V_0402  [FP-C1005-050-0_15-MFG]
C157  20pF_50V_0402  [FP-CBR04C-MFG]
C158  4.7uF_10V_0402  [FP-C1005-050-0_15-MFG]
C159  0.1uF_16V_0402  [FP-C0402-BB-MFG]
D8  LTST-C190GKT  [FP-LTST-C190GKT-MFG]
J8  HTSW-104-07-G-D  [FP-HTSW-104-07-G-D-MFG]  (parts A,B of 2)
L29  742792780  [SMD-0402]
L30  LQM21FN100M80L  [FP-LQM21DH_70-IPC_C]
L31  LQG15HSR10J02D  [FP-LQG15HH_02-IPC_A]
R74  10K_1%_0402  [RESC1005X40X25NL10T10]
R93  330_1%_0402  [RESC1005X40X25NL10T10]
R100  10K_1%_0402  [RESC1005X40X25NL10T10]
R101  10K_1%_0402  [RESC1005X40X25NL10T10]
R102  71.5_1%_0402  [RESC1005X40X25NL05T05]
R103  0_5%_0402  [RESC1005X40X25NL05T10]
R104  0_5%_0402  [RESC1005X40X25NL05T10]
R105  165_1%_0402  [RESC1005X40X25NL05T05]
R106  71.5_1%_0402  [RESC1005X40X25NL05T05]
R107  0_5%_0402  [RESC1005X40X25NL05T10]
R108  0_5%_0402  [RESC1005X40X25NL05T10]
R109  165_1%_0402  [RESC1005X40X25NL05T05]
R110  4.7K_1%_0402  [RESC1005X40X25NL10T10]
R111  4.7K_1%_0402  [RESC1005X40X25NL10T10]
R112  10K_1%_0402  [RESC1005X40X25NL10T10]
R113  DNI_10K_1%_0402  [RESC1005X40X25NL10T10]  (no BOM)
SW3  B3U-1000P  [FP-B3U-1000P-MFG]
SW4  B3U-1000P  [FP-B3U-1000P-MFG]
U7  STM32WL33CCV7  [UFQFPN-48_STM]  (parts A,B of 2)
U8  SN74LVC1G3157DBVR  [FP-DBV0006A-IPC_C]
Y6  NX2012SA-32.768KHZ-EXS00A-MU00389  [FP-NX2012SA-MFG]
Y7  ASE-48.000MHZ-LC-T  [FP-ASE-MFG]

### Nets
GND: C144.2 C145.2 C146.2 C147.2 C148.2 C149.2 C150.2 C151.2 C152.2 C153.2 C154.2 C155.2 C156.2 C157.1 C158.2 C159.2 J8.7 J8.8 R100.2 R105.1 R109.1 R113.2 SW4.2 U7.24(EXTGND) U7.39(VSSSD) U7.49(GND) U8.2(GND) Y7.2(GND/Case)
P3V3: C147.1 C148.1 C151.1 C153.1 C154.1 C155.1 C156.1 C157.2 D8.2(A) J8.2 L29.1 R74.1 R101.1 R110.2 R111.2 R112.1 SW3.2 U7.3(VDD_1) U7.21(VDD2) U7.27(VDDRF) U7.37(VDDSD) U8.5(VCC)
TX_VFBSD: C146.1 C158.1 C159.1 J8.1 L30.1 U7.40(VFBSD)
DPLL_CLKOUT8_N: R107.1 ; off-sheet DPLL_CLKOUT8_N
DPLL_CS: U7.8(PA4) ; off-sheet DPLL_CS
DPLL_GPIO3: U7.7(PA0) ; off-sheet DPLL_GPIO3
DPLL_GPIO4: U7.11(PA9) ; off-sheet DPLL_GPIO4
DPLL_GPIO5: U7.12(PA8) ; off-sheet DPLL_GPIO5
DPLL_RST_N: U7.19(PB14) ; off-sheet DPLL_RST_N
DPLL_SCLK: U7.15(PA6) ; off-sheet DPLL_SCLK
DPLL_SDI: U7.9(PA11) ; off-sheet DPLL_SDI
DPLL_SDIO: U7.16(PA7) ; off-sheet DPLL_SDIO
RX_RST_N: U7.43(PA13) ; off-sheet RX_RST_N
RX_RX_SEQUENCE: U7.42(PA12) ; off-sheet RX_RX_SEQUENCE
RX_SPI1_MISO: U7.34(PB9) ; off-sheet RX_SPI1_MISO
RX_SPI1_MOSI: U7.35(PB8) ; off-sheet RX_SPI1_MOSI
RX_SPI1_NSS: U7.33(PB10) ; off-sheet RX_SPI1_NSS
RX_SPI1_SCK: U7.32(PB11) ; off-sheet RX_SPI1_SCK
RX_SPI3_MISO: U7.31(PB7) ; off-sheet RX_SPI3_MISO
RX_SPI3_MOSI: U7.5(PB4) ; off-sheet RX_SPI3_MOSI
RX_SPI3_NSS: U7.6(PB5) ; off-sheet RX_SPI3_NSS
RX_SPI3_SCK: U7.13(PB6) ; off-sheet RX_SPI3_SCK
RX_TX_SEQUENCE: U7.44(PA14) ; off-sheet RX_TX_SEQUENCE
TX_BOOTSEL: R100.1 SW3.1 U7.10(PA10) ; off-sheet TX_BOOTSEL
TX_CLK: U7.29(OSCIN) U8.4(A) ; off-sheet TX_CLK
TX_CLK_SEL: J8.4 R112.2 R113.1 U8.6(S) ; off-sheet TX_CLK_SEL
TX_DETECT: R74.2 U7.47(PB1) ; off-sheet TX_DETECT
TX_DPLL_48MHz: R108.2 U8.3(B1) ; off-sheet TX_DPLL_48MHz
TX_LCL_48MHz: R104.2 U8.1(B2) ; off-sheet TX_LCL_48MHz
TX_LED0: R93.1 U7.46(PB0) ; off-sheet TX_LED0
TX_LPUART_RX: U7.14(PA5) ; off-sheet TX_LPUART_RX
TX_LPUART_TX: U7.4(PB3) ; off-sheet TX_LPUART_TX
TX_RF_RX: U7.23(RX) ; off-sheet TX_RF_RX
TX_RF_TX: U7.26(TX) ; off-sheet TX_RF_TX
TX_RF_TX_HP: U7.25(TX_HP) ; off-sheet TX_RF_TX_HP
TX_RST_N: R101.2 SW4.1 U7.36(NRST) ; off-sheet TX_RST_N
TX_RX_SPARE0: U7.48(PB2) ; off-sheet TX_RX_SPARE0
TX_RX_SPARE2: U7.20(PB15) ; off-sheet TX_RX_SPARE2
TX_SWCLK: J8.5 R110.1 U7.2(PA3) ; off-sheet TX_SWCLK
TX_SWDIO: J8.3 R111.1 U7.1(PA2) ; off-sheet TX_SWDIO
TX_USART1_RX: U7.45(PA15) ; off-sheet TX_USART1_RX
TX_USART1_TX: U7.30(PA1) ; off-sheet TX_USART1_TX
NetC144_1: C144.1 U7.17(PB12) Y6.1
NetC145_1: C145.1 U7.18(PB13) Y6.2
NetC149_1: C149.1 C150.1 L29.2 Y7.1(~{STBY}) Y7.4(VDD)
NetC152_1: C152.1 U7.41(VCAP)
NetD8_1: D8.1(C) R93.2
NetL30_2: L30.2 L31.1
NetL31_2: L31.2 U7.38(VLXSD)
NetR102_1: R102.1 R103.2
NetR102_2: R102.2 R104.1 R105.2
NetR103_1: R103.1 Y7.3(Output)
NetR106_1: R106.1 R107.2
NetR106_2: R106.2 R108.1 R109.2

Not connected (* = marked no-connect by the designer): J8 6; U7 22(LPAWUR) 28(OSCOUT)

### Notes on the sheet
- Swap MOSI / MISO WRT RX Chip
- (near SW3) PA10 = HIGH AT BOOT -> USART BOOTLOADER
- Divide to about 1V
- (near C151) Clock select multiplexer

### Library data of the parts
C144 C145 = CMP-2008-03875-2: as C128 on sheet 06-STM32WL3-RX
C146 = CMP-14477-000104-2: as C130 on sheet 06-STM32WL3-RX
C147 C149 = CMP-13271-000002-1: as C58 on sheet 02-8A34004_DPLL-1
C148 C150 = CMP-2008-02519-2: as C2 on sheet 01-Antennas
C151 C153-C155 C159 = CMP-1034-02068-3: as C11 on sheet 01-Antennas
C152 = CMP-1034-02089-3: as C136 on sheet 06-STM32WL3-RX
C156 C158 = CMP-2000-05997-2: as C140 on sheet 06-STM32WL3-RX
C157 = CMP-2008-00009-2: as C141 on sheet 06-STM32WL3-RX
D8 = CMP-22017-000005-2: as D1 on sheet 02-8A34004_DPLL-1
J8 = CMP-02766-000066-1: as J7 on sheet 06-STM32WL3-RX
L29 = CMP-0220-00137-1: as L3 on sheet 03-8A34004_DPLL-2
L30 = CMP-06042-014493-1: as L27 on sheet 06-STM32WL3-RX
L31 = CMP-06042-015241-1: as L28 on sheet 06-STM32WL3-RX
R74 R100 R101 R112 R113 = CMP-2002-04694-1: as R73 on sheet 06-STM32WL3-RX
R93 = CMP-2002-05853-1: as R71 on sheet 02-8A34004_DPLL-1
R102 R106 = CMP-2002-00202-1: as R81 on sheet 06-STM32WL3-RX
R103 R104 R107 R108 = CMP-2002-06457-1: as R1 on sheet 01-Antennas
R105 R109 = CMP-2002-08233-1: as R84 on sheet 06-STM32WL3-RX
R110 R111 = CMP-2002-05217-1: as R18 on sheet 02-8A34004_DPLL-1
SW3 SW4 = CMP-2100-03586-2: as SW1 on sheet 06-STM32WL3-RX
U7 = STM32WL33CCV7: as U5 on sheet 06-STM32WL3-RX
U8 = CMP-0859-00203-4: as U6 on sheet 06-STM32WL3-RX
Y6 = CMP-200220-000005-1: as Y3 on sheet 06-STM32WL3-RX
Y7 = CMP-27762-000273-1: as Y5 on sheet 06-STM32WL3-RX

## Sheet 08-Power.SchDoc
size B; SheetNumber: 8; SheetTotal: 8
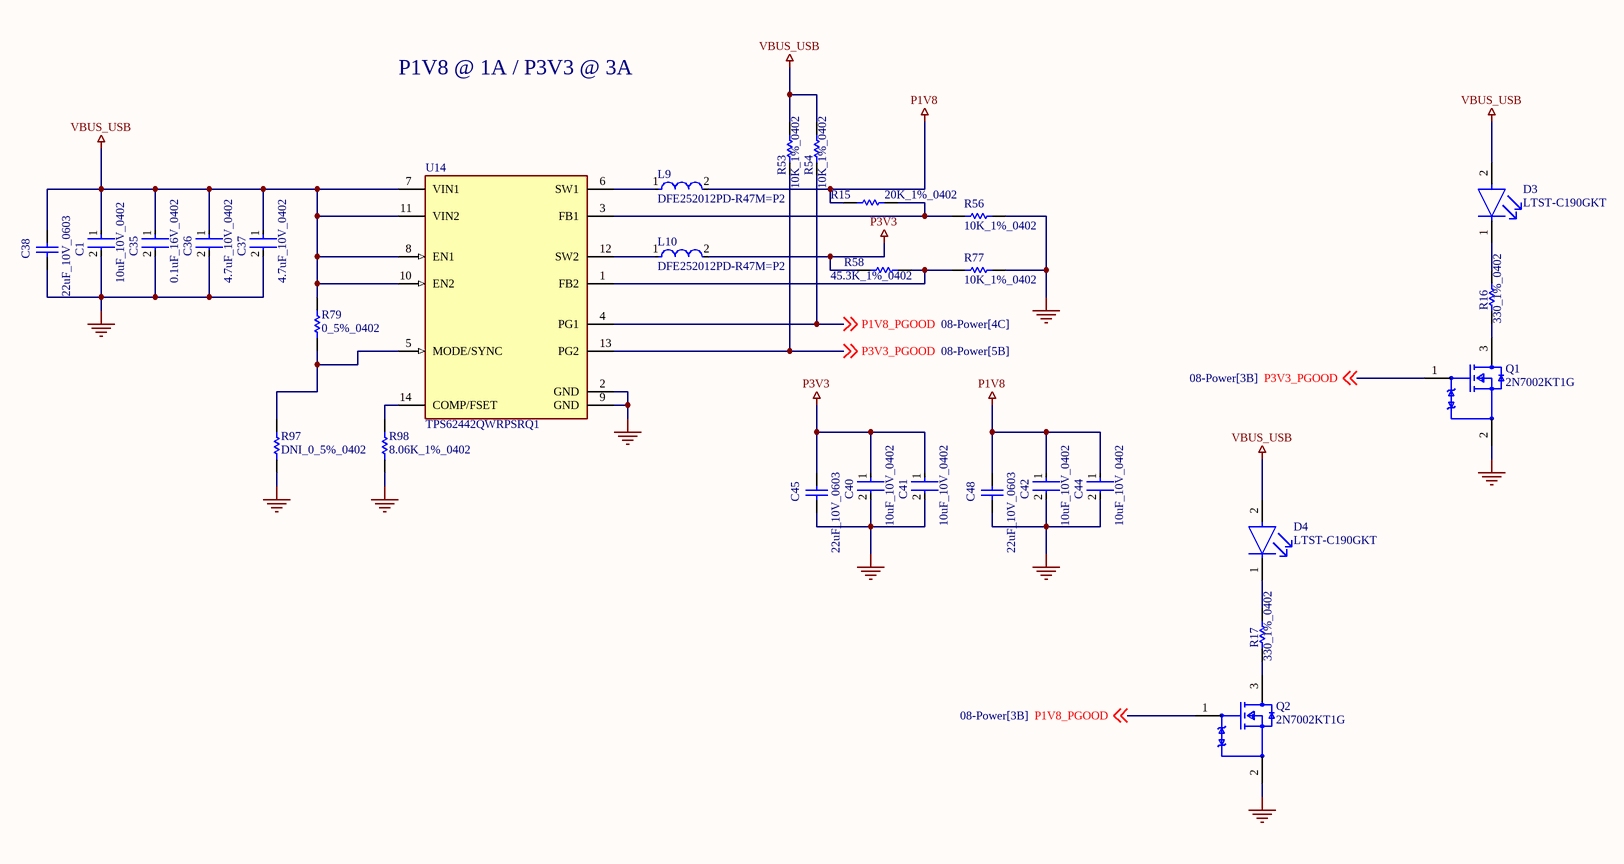
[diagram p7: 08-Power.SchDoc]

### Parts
C1  10uF_10V_0402  [FP-CL05A106MP5NUNC-MFG]
C35  0.1uF_16V_0402  [FP-C0402-BB-MFG]
C36  4.7uF_10V_0402  [FP-C1005-050-0_15-MFG]
C37  4.7uF_10V_0402  [FP-C1005-050-0_15-MFG]
C38  22uF_10V_0603  [CAPC1608X100X20ML10]
C40  10uF_10V_0402  [FP-CL05A106MP5NUNC-MFG]
C41  10uF_10V_0402  [FP-CL05A106MP5NUNC-MFG]
C42  10uF_10V_0402  [FP-CL05A106MP5NUNC-MFG]
C44  10uF_10V_0402  [FP-CL05A106MP5NUNC-MFG]
C45  22uF_10V_0603  [CAPC1608X100X20ML10]
C48  22uF_10V_0603  [CAPC1608X100X20ML10]
D3  LTST-C190GKT  [FP-LTST-C190GKT-MFG]
D4  LTST-C190GKT  [FP-LTST-C190GKT-MFG]
L9  DFE252012PD-R47M=P2  [FP-DFE252012C-IPC_A]
L10  DFE252012PD-R47M=P2  [FP-DFE252012C-IPC_A]
Q1  2N7002KT1G  [FP-318-08-MFG]
Q2  2N7002KT1G  [FP-318-08-MFG]
R15  20K_1%_0402  [RESC1005X40X25ML10T10]
R16  330_1%_0402  [RESC1005X40X25NL10T10]
R17  330_1%_0402  [RESC1005X40X25NL10T10]
R53  10K_1%_0402  [RESC1005X40X25NL10T10]
R54  10K_1%_0402  [RESC1005X40X25NL10T10]
R56  10K_1%_0402  [RESC1005X40X25NL10T10]
R58  45.3K_1%_0402  [RESC0402(1005)_L]
R77  10K_1%_0402  [RESC1005X40X25NL10T10]
R79  0_5%_0402  [RESC1005X40X25NL05T10]
R97  DNI_0_5%_0402  [RESC1005X40X25NL05T10]  (no BOM)
R98  8.06K_1%_0402  [RESC1005X40X25ML05T05]
U14  TPS62442QWRPSRQ1  [FP-RQR0014A-MFG]

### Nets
GND: C1.2 C35.2 C36.2 C37.2 C38.1 C40.2 C41.2 C42.2 C44.2 C45.1 C48.1 Q1.2(Source) Q2.2(Source) R56.1 R77.1 R97.1 R98.1 U14.2(GND) U14.9(GND)
P1V8: C42.1 C44.1 C48.2 L9.2 R15.1
P3V3: C40.1 C41.1 C45.2 L10.2 R58.1
VBUS_USB: C1.1 C35.1 C36.1 C37.1 C38.2 D3.2(A) D4.2(A) R53.2 R54.2 R79.2 U14.7(VIN1) U14.8(EN1) U14.10(EN2) U14.11(VIN2)
P1V8_PGOOD: Q2.1(Gate) R54.1 U14.4(PG1) ; off-sheet P1V8_PGOOD
P3V3_PGOOD: Q1.1(Gate) R53.1 U14.13(PG2) ; off-sheet P3V3_PGOOD
NetD3_1: D3.1(C) R16.2
NetD4_1: D4.1(C) R17.2
NetL9_1: L9.1 U14.6(SW1)
NetL10_1: L10.1 U14.12(SW2)
NetQ1_3: Q1.3(Drain) R16.1
NetQ2_3: Q2.3(Drain) R17.1
NetR15_2: R15.2 R56.2 U14.3(FB1)
NetR58_2: R58.2 R77.2 U14.1(FB2)
NetR79_1: R79.1 R97.2 U14.5(MODE/SYNC)
NetR98_2: R98.2 U14.14(COMP/FSET)

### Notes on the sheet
- P1V8 @ 1A / P3V3 @ 3A

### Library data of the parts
C1 C40-C42 C44 = CMP-13271-000002-1: as C58 on sheet 02-8A34004_DPLL-1
C35 = CMP-1034-02068-3: as C11 on sheet 01-Antennas
C36 C37 = CMP-2000-05997-2: as C140 on sheet 06-STM32WL3-RX
C38 C45 C48 = CMP-2000-05441-1: Chip Capacitor, 22 uF, +/- 20%, 10 V, -55 to 85 degC, 0603 (1608 Metric), RoHS, Tape and Reel; Manufacturer: TDK; PCN Part Number: MLCCPartNumberChange30/Nov/2012; Voltage - Rated: 10V; Product Training Modules: CSeriesGeneralApplicationsSEAT,CCV,andTVCLDesignToolsGuidetoReplacinganElectrolyticCapacitorwithanMLCC; Other Names: 445-9077-1; Design Resources: 20WNon-IsolatedBuckLEDDriverUsingPLLNK460KG; Online Catalog: CSeries,GeneralPurpose; Capacitance: 22µF; Temperature Coefficient: X5R; Kits: 445-9014-KIT-ND-KITMLCC100PF-22UF060310-50V
D3 D4 = CMP-22017-000005-2: as D1 on sheet 02-8A34004_DPLL-1
L9 L10 = CMP-06042-015149-1: Shielded Wirewound Inductor 0.47uH 20% 4000mA 0.027Ω 1008 (2520)
Q1 Q2 = CMP-1058-00766-2: MOSFET N-CH 60V 320MA SOT-23; Max Power Dissipation: 420mW; Nominal Vgs: 2.3V; Fall Time: 9ns; Turn-Off Delay Time: 55.8ns; Number of Elements: 1; Rds On Max: 1.6R; Input Capacitance: 24.5pF; Turn-On Delay Time: 12.2ns; Element Configuration: Single; Gate to Source Voltage (Vgs): 20V; Power Dissipation: 300mW
R15 = CMP-2002-05709-1: Manufacturer: TE Connectivity / AMP; Part Number: CRG0402F20K
R16 R17 = CMP-2002-05853-1: as R71 on sheet 02-8A34004_DPLL-1
R53 R54 R56 R77 = CMP-2002-04694-1: as R73 on sheet 06-STM32WL3-RX
R58 = CMP-1011-00697-1: 45K3 0.063W 1% 0402 (1005 Metric)  SMD; Case-EIA: 0402; Case-Metric: 1005; Value: 45300.00 Ohm
R79 R97 = CMP-2002-06457-1: as R1 on sheet 01-Antennas
R98 = CMP-2002-00253-3: Chip Resistor, 8.06 KOhm, +/- 1%, 63 mW, -55 to 155 degC, 0402 (1005 Metric), RoHS, Tape and Reel; PartNumber: CRCW04028K06FKED; Manufacturer: Basic Passives; Case\/Package: 0402; Power Rating: 63 mW; Voltage Rating: 50 V
U14 = CMP-04918-000654-1: Adjustable-Frequency Dual Step-Down Converter, 2.7-6V VIN, 0.6-5.5V 2A VOUT, VQFN-HR14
